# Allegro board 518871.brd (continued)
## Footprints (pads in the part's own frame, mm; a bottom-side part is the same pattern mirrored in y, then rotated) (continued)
JMP402-25
  rect 0.635x0.635 smd: 1(-0.508,0)
  round 0.635 smd: 2(0.508,0) 3(1.524,0)
JUMP1X2-6040
  rect 1.524x1.524 hole 1.016: 1(0,0)
  round 1.524 hole 1.016: 2(0,-2.54)
L603-35X45
  oval 0.889x1.143 smd: 1(-0.762,0) 2(0.762,0)
L805-35X60
  oval 0.889x1.524 smd: 1(-0.965,0) 2(0.965,0)
LED1206-59X59
  rect 1.499x1.499 smd: 1(-1.753,0) 2(1.753,0)
MHP125-250
  round 6.35 hole 3.175: 1(0,0)
MOLEX4-043650
  round 1.016 hole 2.997 unplated: (-6.833,-4.318) (-2.134,-4.318)
  rect 2.032x2.032 hole 1.041: 1(0,0)
  round 2.032 hole 1.041: 2(-2.997,0) 3(-5.994,0) 4(-8.992,0)
MOLEX-34826-0124
  round 1.524 hole 0.991: 1(-7.01,1.295) 2(-5.004,1.295) 3(5.004,1.295) 4(7.01,1.295) 5(-7.01,-0.914) 6(-5.004,-0.914) 7(-2.997,-0.914) 8(-0.991,-0.914) 9(0.991,-0.914) 10(2.997,-0.914) 11(5.004,-0.914) 12(7.01,-0.914)
  round 3.556 hole 2.54: 13(-9.855,0) 14(9.855,0)
MOLEX-502774-0891
  rect 0.787x1.778 smd: 1(-2.784,7.366) 2(-1.684,7.366) 3(-0.584,7.366) 4(0.516,7.366) 5(1.615,7.366) 6(2.715,7.366) 7(3.815,7.366) 8(4.915,7.366)
  rect 1.295x1.397 smd: 9(6.985,-1.6)
  rect 1.295x1.245 smd: 10(6.985,5.842)
  rect 1.778x2.032 smd: 11(6.858,-7.417) 12(-6.655,-7.391)
  rect 1.854x1.778 smd: 13(-6.35,7.468) 14(6.452,7.595)
PWR-Q5A-SLPS319
  rect 0.711x1.397 smd: 1(-1.905,0) 2(-0.635,0) 3(0.635,0) 4(1.905,0)
  custom 1.111x1.111 smd: 5(0,2.781)
QFN32_5X5
  oval 0.254x0.838 smd: 1(-1.751,-2.515) 8(1.751,-2.515) 17(1.751,2.515) 24(-1.751,2.515)
  rect 0.254x0.838 smd: 2(-1.251,-2.515) 3(-0.751,-2.515) 4(-0.25,-2.515) 5(0.25,-2.515) 6(0.751,-2.515) 7(1.251,-2.515) 18(1.251,2.515) 19(0.751,2.515) 20(0.25,2.515) 21(-0.25,2.515) 22(-0.751,2.515) 23(-1.251,2.515)
  oval 0.838x0.254 smd: 9(2.515,-1.751) 16(2.515,1.751) 25(-2.515,1.751) 32(-2.515,-1.751)
  rect 0.838x0.254 smd: 10(2.515,-1.251) 11(2.515,-0.751) 12(2.515,-0.25) 13(2.515,0.25) 14(2.515,0.751) 15(2.515,1.251) 26(-2.515,1.251) 27(-2.515,0.751) 28(-2.515,0.25) 29(-2.515,-0.25) 30(-2.515,-0.751) 31(-2.515,-1.251)
  rect 3.404x3.404 smd: 33(0,0)
QSH-020-DP-A
  round 0.508 hole 1.016 unplated: (-10.06,2.667) (10.06,2.667)
  rect 0.279x2.273 smd: 1(-7.248,-2.864) 2(-7.248,2.864) 3(-6.748,-2.864) 4(-6.748,2.864) 5(-5.749,-2.864) 6(-5.749,2.864) 7(-5.249,-2.864) 8(-5.249,2.864) 9(-4.249,-2.864) 10(-4.249,2.864) 11(-3.749,-2.864) 12(-3.749,2.864) 13(-2.749,-2.864) 14(-2.749,2.864) 15(-2.249,-2.864) 16(-2.249,2.864) 17(-1.25,-2.864) 18(-1.25,2.864) 19(-0.75,-2.864) 20(-0.75,2.864) 21(0.25,-2.864) 22(0.25,2.864) 23(0.75,-2.864) 24(0.75,2.864) 25(1.75,-2.864) 26(1.75,2.864) 27(2.249,-2.864) 28(2.249,2.864) 29(3.249,-2.864) 30(3.249,2.864) 31(3.749,-2.864) 32(3.749,2.864) 33(4.749,-2.864) 34(4.749,2.864) 35(5.249,-2.864) 36(5.249,2.864) 37(6.248,-2.864) 38(6.248,2.864) 39(6.748,-2.864) 40(6.748,2.864)
  rect 2.54x0.432 smd: 41(-8.065,0) 44(8.065,0)
  rect 4.699x0.432 smd: 42(-3.175,0) 43(3.175,0)
QSH-030-01-F
  round 0.508 hole 1.016 unplated: (-10.061,2.667) (10.061,2.667)
  rect 0.279x2.273 smd: 1(-7.249,-2.865) 2(-7.249,2.865) 3(-6.749,-2.865) 4(-6.749,2.865) 5(-6.248,-2.865) 6(-6.248,2.865) 7(-5.748,-2.865) 8(-5.748,2.865) 9(-5.248,-2.865) 10(-5.248,2.865) 11(-4.75,-2.865) 12(-4.75,2.865) 13(-4.249,-2.865) 14(-4.249,2.865) 15(-3.749,-2.865) 16(-3.749,2.865) 17(-3.249,-2.865) 18(-3.249,2.865) 19(-2.748,-2.865) 20(-2.748,2.865) 21(-2.25,-2.865) 22(-2.25,2.865) 23(-1.75,-2.865) 24(-1.75,2.865) 25(-1.25,-2.865) 26(-1.25,2.865) 27(-0.749,-2.865) 28(-0.749,2.865) 29(-0.249,-2.865) 30(-0.249,2.865) 31(0.249,-2.865) 32(0.249,2.865) 33(0.749,-2.865) 34(0.749,2.865) 35(1.25,-2.865) 36(1.25,2.865) 37(1.75,-2.865) 38(1.75,2.865) 39(2.25,-2.865) 40(2.25,2.865) 41(2.748,-2.865) 42(2.748,2.865) 43(3.249,-2.865) 44(3.249,2.865) 45(3.749,-2.865) 46(3.749,2.865) 47(4.249,-2.865) 48(4.249,2.865) 49(4.75,-2.865) 50(4.75,2.865) 51(5.248,-2.865) 52(5.248,2.865) 53(5.748,-2.865) 54(5.748,2.865) 55(6.248,-2.865) 56(6.248,2.865) 57(6.749,-2.865) 58(6.749,2.865) 59(7.249,-2.865) 60(7.249,2.865)
  rect 2.54x0.432 smd: 61(-8.065,0) 64(8.065,0)
  rect 4.699x0.432 smd: 62(-3.175,0) 63(3.175,0)
R201-6P6SPC
  rect 0.47x0.381 smd: 1(-0.343,0) 2(0.343,0)
R402-25
  round 0.635 smd: 1(-0.508,0) 2(0.508,0)
R603-35X45
  oval 0.889x1.143 smd: 1(-0.762,0) 2(0.762,0)
R0612
  rect 3.175x0.889 smd: 1(0,-0.813) 2(0,0.813)
R1206-40X70
  oval 1.016x1.778 smd: 1(-1.524,0) 2(1.524,0)
RGE24-11X28-4MM
  rect 0.711x0.279 smd: 1(-1.905,1.245) 2(-1.905,0.747) 3(-1.905,0.249) 4(-1.905,-0.249) 5(-1.905,-0.747) 6(-1.905,-1.245) 13(1.905,-1.245) 14(1.905,-0.747) 15(1.905,-0.249) 16(1.905,0.249) 17(1.905,0.747) 18(1.905,1.245)
  rect 0.279x0.711 smd: 7(-1.245,-1.905) 8(-0.747,-1.905) 9(-0.249,-1.905) 10(0.249,-1.905) 11(0.747,-1.905) 12(1.245,-1.905) 19(1.245,1.905) 20(0.747,1.905) 21(0.249,1.905) 22(-0.249,1.905) 23(-0.747,1.905) 24(-1.245,1.905)
  rect 2.464x2.464 smd: 25(0,0)
RKT24
  rect 0.203x0.965 smd: 1(-1.806,-0.965) 2(-1.405,-0.965) 3(-1.003,-0.965) 4(-0.602,-0.965) 5(-0.201,-0.965) 6(0.201,-0.965) 7(0.602,-0.965) 8(1.003,-0.965) 9(1.405,-0.965) 10(1.806,-0.965) 13(1.806,0.965) 14(1.405,0.965) 15(1.003,0.965) 16(0.602,0.965) 17(0.201,0.965) 18(-0.201,0.965) 19(-0.602,0.965) 20(-1.003,0.965) 21(-1.405,0.965) 22(-1.806,0.965)
  rect 0.965x0.203 smd: 11(1.981,-0.201) 12(1.981,0.201) 23(-1.981,0.201) 24(-1.981,-0.201)
RND36-24X10
  oval 0.254x0.61 smd: 1(-2.002,-2.896) 2(-1.501,-2.896) 3(-1.001,-2.896) 4(-0.5,-2.896) 5(0,-2.896) 6(0.498,-2.896) 7(0.998,-2.896) 8(1.499,-2.896) 9(1.999,-2.896) 19(2.002,2.896) 20(1.501,2.896) 21(1.001,2.896) 22(0.5,2.896) 23(0,2.896) 24(-0.498,2.896) 25(-0.998,2.896) 26(-1.499,2.896) 27(-1.999,2.896)
  oval 0.61x0.254 smd: 10(2.896,-2.002) 11(2.896,-1.501) 12(2.896,-1.001) 13(2.896,-0.5) 14(2.896,0) 15(2.896,0.498) 16(2.896,0.998) 17(2.896,1.499) 18(2.896,1.999) 28(-2.896,1.999) 29(-2.896,1.499) 30(-2.896,0.998) 31(-2.896,0.498) 32(-2.896,0) 33(-2.896,-0.5) 34(-2.896,-1.001) 35(-2.896,-1.501) 36(-2.896,-2.002)
  rect 3.81x3.81 smd: 37(0,0)
RTD64
  rect 0.711x0.279 smd: 1(-4.445,3.749) 2(-4.445,3.249) 3(-4.445,2.749) 4(-4.445,2.249) 5(-4.445,1.75) 6(-4.445,1.25) 7(-4.445,0.75) 8(-4.445,0.25) 9(-4.445,-0.25) 10(-4.445,-0.75) 11(-4.445,-1.25) 12(-4.445,-1.75) 13(-4.445,-2.249) 14(-4.445,-2.749) 15(-4.445,-3.249) 16(-4.445,-3.749) 33(4.445,-3.749) 34(4.445,-3.249) 35(4.445,-2.749) 36(4.445,-2.249) 37(4.445,-1.75) 38(4.445,-1.25) 39(4.445,-0.75) 40(4.445,-0.25) 41(4.445,0.25) 42(4.445,0.75) 43(4.445,1.25) 44(4.445,1.75) 45(4.445,2.249) 46(4.445,2.749) 47(4.445,3.249) 48(4.445,3.749)
  rect 0.279x0.711 smd: 17(-3.749,-4.445) 18(-3.249,-4.445) 19(-2.749,-4.445) 20(-2.249,-4.445) 21(-1.75,-4.445) 22(-1.25,-4.445) 23(-0.75,-4.445) 24(-0.25,-4.445) 25(0.25,-4.445) 26(0.75,-4.445) 27(1.25,-4.445) 28(1.75,-4.445) 29(2.249,-4.445) 30(2.749,-4.445) 31(3.249,-4.445) 32(3.749,-4.445) 49(3.749,4.445) 50(3.249,4.445) 51(2.749,4.445) 52(2.249,4.445) 53(1.75,4.445) 54(1.25,4.445) 55(0.75,4.445) 56(0.25,4.445) 57(-0.25,4.445) 58(-0.75,4.445) 59(-1.25,4.445) 60(-1.75,4.445) 61(-2.249,4.445) 62(-2.749,4.445) 63(-3.249,4.445) 64(-3.749,4.445)
  rect 5.588x5.588 smd: 65(0,0)
SAMTEC-MUSB
  round 0.508 hole 0.889 unplated: (-2.197,-2.591) (2.197,-2.591)
  rect 0.508x2.286 smd: 1(-1.6,0) 2(-0.8,0) 3(0,0) 4(0.8,0) 5(1.6,0)
  rect 2.007x2.489 smd: 6(-4.445,-0.102) 7(4.445,-0.102) 8(-4.445,-5.613) 9(4.445,-5.613)
SM-7351-CAP-0402
  round 0.635 smd: 1(-0.508,0) 2(0.508,0)
SM-7351-CAP-0508
  rect 0.457x1.778 smd: 1(-0.445,0) 2(0.445,0)
SM-7351-RES-0402
  round 0.635 smd: 1(-0.508,0) 2(0.508,0)
SMA2-78SQ
  rect 1.981x1.981 smd: 1(-2.007,0) 2(2.007,0)
SMC-80X128
  rect 2.032x3.251 smd: 1(-3.124,0) 2(3.124,0)
SO8-25X75-295
  oval 0.635x2.54 smd: 1(-1.905,-3.086) 2(-0.635,-3.086) 3(0.635,-3.086) 4(1.905,-3.086) 5(1.905,3.086) 6(0.635,3.086) 7(-0.635,3.086) 8(-1.905,3.086)
SO14-25X75
  oval 0.635x1.905 smd: 1(-3.81,-2.794) 2(-2.54,-2.794) 3(-1.27,-2.794) 4(0,-2.794) 5(1.27,-2.794) 6(2.54,-2.794) 7(3.81,-2.794) 8(3.81,2.794) 9(2.54,2.794) 10(1.27,2.794) 11(0,2.794) 12(-1.27,2.794) 13(-2.54,2.794) 14(-3.81,2.794)
SOD323
  rect 1.092x0.508 smd: 1(-1.194,0) 2(1.194,0)
SOT363-16X45
  rect 0.406x0.635 smd: 1(-0.65,-0.978) 2(0,-0.978) 3(0.65,-0.978) 4(0.65,0.978) 5(0,0.978) 6(-0.65,0.978)
SW2-30X50-TDA
  rect 0.762x1.27 smd: 1(-0.635,-3.81) 2(0.635,-3.81) 3(0.635,3.81) 4(-0.635,3.81)
SW6-30X50-TDA
  rect 0.762x1.27 smd: 1(-3.175,-3.81) 2(-1.905,-3.81) 3(-0.635,-3.81) 4(0.635,-3.81) 5(1.905,-3.81) 6(3.175,-3.81) 7(3.175,3.81) 8(1.905,3.81) 9(0.635,3.81) 10(-0.635,3.81) 11(-1.905,3.81) 12(-3.175,3.81)
TP1-70X135
  rect 2.286x3.937 smd: 1(0,0)
TP-30RD13
  round 0.762 hole 0.33: 1(0,0)
TSDSON8
  custom 0.248x0.248 smd: 1(-0.33,-1.499)
  rect 0.356x1.016 smd: 4(0.978,-1.486)
  custom 0.572x0.572 smd: 5(0,0.673)
unnamed
  round 1.27 smd: 1(0,0)
VFP0032B
  rect 1.346x0.508 smd: 1(-4.125,2.799) 2(-4.125,1.999) 3(-4.125,1.199) 4(-4.125,0.401) 5(-4.125,-0.401) 6(-4.125,-1.199) 7(-4.125,-1.999) 8(-4.125,-2.799) 17(4.125,-2.799) 18(4.125,-1.999) 19(4.125,-1.199) 20(4.125,-0.401) 21(4.125,0.401) 22(4.125,1.199) 23(4.125,1.999) 24(4.125,2.799)
  rect 0.508x1.346 smd: 9(-2.799,-4.125) 10(-1.999,-4.125) 11(-1.199,-4.125) 12(-0.401,-4.125) 13(0.401,-4.125) 14(1.199,-4.125) 15(1.999,-4.125) 16(2.799,-4.125) 25(2.799,4.125) 26(1.999,4.125) 27(1.199,4.125) 28(0.401,4.125) 29(-0.401,4.125) 30(-1.199,4.125) 31(-1.999,4.125) 32(-2.799,4.125)
  rect 4.826x4.826 smd: 33(0,0)
VQFNHR26
  custom 0.194x0.194 smd: 1(-1.816,2.038) 8(-1.816,-2.038) 14(1.81,-2.038) 21(1.81,2.038)
  rect 0.597x0.254 smd: 2(-1.899,1.25) 3(-1.899,0.749) 4(-1.899,0.249) 5(-1.899,-0.249) 6(-1.899,-0.749) 7(-1.899,-1.25) 15(1.899,-1.25) 16(1.899,-0.749) 17(1.899,-0.249) 18(1.899,0.249) 19(1.899,0.749) 20(1.899,1.25)
  rect 0.254x1.816 smd: 9(-1.001,-1.537) 10(-0.5,-1.537) 11(0,-1.537) 12(0.5,-1.537) 13(1.001,-1.537) 22(1.001,1.537) 23(0.5,1.537) 24(0,1.537) 25(-0.5,1.537) 26(-1.001,1.537)
  rect 2.235x0.66 smd: 27(0,0)
XTAL4-ABM11
  rect 0.889x0.813 smd: 1(-0.711,-0.559) 2(0.711,-0.559) 3(0.711,0.559) 4(-0.711,0.559)

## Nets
1V8_I2C1_SCL: P9.2 R245.2 U26.3(SCL1)
1V8_I2C1_SDA: P9.4 R246.2 U26.4(SDA1)
1V8_RSTOUTN: P9.14 R296.1 U31.M5(RSTN) U54.4(O)
GND: C1.2 C2.2 C3.2 C8.2 C23.2 C24.2 C29.2 C37.2 C38.2 C40.2 C41.1 C43.1 C45.2 C48.1 C51.1 C53.2 C54.1 C56.2 C59.2 C64.2 C71.2 C72.2 C73.2 C78.2 C81.2 C82.2 C83.2 C84.2 C89.2 C91.2 C96.2 C98.2 C108.2 C114.2 C118.2 C119.2 C120.2 C122.2 C129.2 C143.1 C144.1 C153.1 C154.1 C155.1 C156.1 C157.1 C158.1 C160.1 C161.1 C163.1 C164.1 C189.2 C194.2 C203.2 C204.2 C212.2 C267.2 C268.2 C269.2 C272.2 C273.2 C274.2 C275.1 C277.2 C278.2 C279.2 C280.2 C281.2 C282.2 C283.2 C284.2 C285.2 C286.2 C287.2 C288.2 C289.2 C293.2 C294.2 C295.2 C296.2 C297.2 C298.2 C299.2 C300.2 C301.2 C302.2 C303.2 C304.2 C305.2 C306.2 C307.2 C308.2 C309.2 C310.2 C311.2 C312.2 C313.2 C314.2 C315.2 C318.2 C319.2 C320.2 C321.2 C322.2 C323.2 C324.2 C325.2 C326.2 C327.2 C328.2 C329.2 C331.2 C332.2 C333.2 C334.2 C335.2 C336.2 C337.2 C338.2 C340.2 C341.2 C342.2 C343.2 C344.2 C345.2 C347.2 C348.2 C349.2 C351.2 C352.2 C354.2 C356.2 C357.2 C358.2 C359.2 C361.2 C362.2 C364.2 C367.2 C368.2 C369.2 C370.2 C372.2 C373.2 C374.2 C375.1 C377.2 C378.2 C379.2 C380.2 C382.2 C383.2 C385.2 C388.2 C390.2 C391.2 C392.2 C393.2 C394.2 C395.2 C401.2 C402.2 C403.2 C406.2 C407.2 C408.2 C409.2 C410.2 C411.2 C412.2 C426.2 C427.2 C428.2 C429.2 C430.2 C431.2 C432.2 C433.2 C434.2 C435.2 C436.2 C437.2 C442.1 C503.2 C506.2 C507.2 C508.2 C509.2 C511.2 C514.2 C518.2 C519.2 C521.2 C525.2 C536.2 C537.2 C540.2 C541.2 C542.2 C543.2 C544.2 C545.2 C546.2 C547.2 C551.2 C552.2 C553.2 C554.1 C556.2 C557.2 C558.2 C559.2 C560.2 C561.2 C562.2 C563.2 C565.2 C566.2 C567.2 C568.2 C569.1 C600.1 C601.2 C602.2 C603.1 C604.2 C605.2 C606.2 C607.2 C608.2 C609.2 C610.2 C611.1 C612.2 C613.2 C614.2 C615.2 C616.2 C617.1 C618.2 C619.2 C620.2 C621.2 C622.2 C623.2 C624.2 C625.2 C626.2 C627.2 C628.2 C629.2 C631.1 C632.1 C633.1 C634.1 C635.1 C638.1 C640.1 C641.1 C642.1 D21.1(CATHODE) D23.2(ANODE) D24.2(ANODE) D26.2(ANODE) D27.2(ANODE) DS1.1(CATHODE) E1.2 E2.2 E3.2 E4.2 E5.2 E6.2 E7.2 J1.2 J4.2 J7.5(USBVSS) J14.16(GND16) J14.57(GND57) J14.58(GND58) J14.61(GNDCT1) J14.62(GNDCT2) J14.63(GNDCT3) J14.64(GNDCT4) J17.5 J17.6 J17.11 J17.12 J25.1 J25.2 J25.8 J25.10 J25.12 J25.15 J25.18 J25.21 J25.24 J25.27 J25.30 J25.33 J25.36 J25.39 J25.40 J25.41(M1) J25.42(M2) J25.43(M3) J25.44(M4) J25.45(M5) J25.46(M6) J25.47(M7) J25.48(M8) J25.49(M9) J25.50(M10) M1.1 M2.1 M3.1 M4.1 P1.2(D2 SHIELD) P1.5(D1 SHIELD) P1.8(D0 SHIELD) P1.11(CK SHIELD) P1.17(GND) P1.MTG1 P1.MTG2 P1.MTG3 P1.MTG4 P9.12 P9.16 P9.24 P9.41(SH_GND.1) P9.42(SH_GND.2) P9.43(SH_GND.4) P9.44(SH_GND.3) P10.6(VSS) Q10.1(S) Q12.1(S2) Q12.4(S2) Q600.1(S2) Q600.4(S2) Q602.4(S2) R26.1 R32.2 R36.1 R39.1 R52.2 R56.1 R64.2 R76.2 R104.1 R118.1 R141.1 R222.1 R225.2 R235.2 R240.1 R244.1 R248.1 R251.2 R255.2 R259.2 R309.1 R330.2 R401.2 R409.2 R432.2 R437.2 R440.1 R441.1 R443.2 R444.2 R446.2 R448.1 R600.2 R603.1 R604.1 R608.1 R622.1 R623.1 RJ16.3 RJ17.3 RJ18.1 RJ19.1 RJ20.1 RJ21.1 RJ22.1 RJ23.1 RJ24.1 RJ25.1 RJ27.3 RJ28.3 RJ29.3 RJ30.3 TP16.1 TP17.1 TP39.1 TP60.1 TP63.1 TP64.1 TP65.1 TP66.1 U3.2(GND) U4.2(GND) U5.2(GND) U6.2(GND) U7.2(GND) U8.2(GND) U9.2(GND) U10.2(GND) U17.5(GND1) U17.13(GND2) U17.18(GND3) U18.3(AGND) U18.9(PGND) U18.25(DAP) U22.1(A0) U22.2(A1) U22.3(NC) U22.4(VSS) U23.A9(VSS.1) U23.B1(VSSQ.1) U23.B3(VSS.2) U23.B9(VSSQ.2) U23.D1(VSSQ.3) U23.D8(VSSQ.4) U23.E1(VSS.3) U23.E2(VSSQ.5) U23.E8(VSSQ.6) U23.F9(VSSQ.7) U23.G1(VSSQ.8) U23.G8(VSS.4) U23.G9(VSSQ.9) U23.J2(VSSDL) U23.J8(VSS.5) U23.M1(VSS.6) U23.M9(VSS.7) U23.P1(VSS.8) U23.P9(VSS.9) U23.T1(VSS.10) U23.T9(VSS.11) U26.1(GND) U27.A1(VSS_1) U27.A25(VSS_2) U27.AA7(VSS_78) U27.AA8(VSS_79) U27.AA9(VSS_80) U27.AA13(VSS_27) U27.AA15(VSS_86) U27.AB8(VSS_81) U27.AB11(VSSA_OSC1) U27.AC11(XI_OSC1) U27.AC13(VSS_82) U27.AE1(VSS_83) U27.AE15(VSS_84) U27.AE25(VSS_85) U27.G8(VSS_3) U27.G13(VSS_4) U27.G16(VSS_5) U27.H8(VSS_6) U27.H10(VSS_7) U27.H12(VSS_8) U27.H14(VSS_9) U27.H16(VSS_10) U27.H18(VSS_11) U27.H19(VSS_12) U27.J10(VSS_13) U27.J12(VSS_14) U27.J14(VSS_15) U27.J17(VSS_16) U27.K9(VSS_17) U27.K11(VSS_18) U27.K13(VSS_19) U27.K15(VSS_20) U27.K17(VSS_21) U27.L8(VSS_22) U27.L11(VSS_23) U27.L13(VSS_24) U27.L15(VSS_25) U27.L18(VSS_26) U27.M8(VSS_28) U27.M9(VSS_29) U27.M12(VSS_30) U27.M14(VSS_31) U27.M16(VSS_32) U27.M18(VSS_33) U27.M20(VSS_34) U27.N12(VSS_35) U27.N14(VSS_36) U27.N16(VSS_37) U27.N17(VSS_38) U27.N20(VSS_39) U27.P9(VSS_40) U27.P11(VSS_41) U27.P13(VSS_42) U27.P15(VSS_43) U27.P17(VSS_44) U27.P19(VSS_45) U27.R8(VSS_46) U27.R9(VSS_47) U27.R11(VSS_48) U27.R13(VSS_49) U27.R15(VSS_50) U27.R18(VSS_51) U27.R19(VSS_52) U27.T8(VSS_53) U27.T10(VSS_54) U27.T12(VSS_55) U27.T14(VSS_56) U27.T16(VSS_57) U27.T18(VSS_58) U27.U10(VSS_59) U27.U12(VSS_60) U27.U14(VSS_61) U27.U16(VSS_62) U27.U17(VSS_63) U27.U19(VSS_64) U27.V8(VSS_65) U27.V9(VSS_66) U27.V11(VSS_67) U27.V13(VSS_68) U27.V15(VSS_69) U27.V17(VSS_70) U27.V19(VSS_71) U27.W9(VSS_72) U27.W19(VSS_73) U27.Y7(VSS_74) U27.Y14(VSS_75) U27.Y16(VSS_76) U27.Y17(VSS_77) U29.A9(VSS.1) U29.B1(VSSQ.1) U29.B3(VSS.2) U29.B9(VSSQ.2) U29.D1(VSSQ.3) U29.D8(VSSQ.4) U29.E1(VSS.3) U29.E2(VSSQ.5) U29.E8(VSSQ.6) U29.F9(VSSQ.7) U29.G1(VSSQ.8) U29.G8(VSS.4) U29.G9(VSSQ.9) U29.J2(VSSDL) U29.J8(VSS.5) U29.M1(VSS.6) U29.M9(VSS.7) U29.P1(VSS.8) U29.P9(VSS.9) U29.T1(VSS.10) U29.T9(VSS.11) U31.G2(VSS.1) U31.G3(VSS.2) U31.G4(VSS.3) U31.G5(VSS.4) U31.G6(VSS.5) U31.G7(VSS.6) U31.G8(VSS.7) U31.G9(VSS.8) U31.H2(VSSQ.1) U31.H9(VSSQ.2) U31.J5(VSS.9) U31.L3(VSSQ.3) U31.L8(VSSQ.4) U31.M4(VSSQ.5) U31.M7(VSSQ.6) U31.P2(VSSQ.7) U31.P9(VSSQ.8) U35.4(PGND) U35.8(GND) U35.11(PWRPAD) U40.37(GND) U42.1(GND) U42.9(PAD) U52.4(GND.1) U52.17(GND.2) U52.20(GND.3) U52.24(AGND) U52.26(TEST) U52.33(PWRPAD) U54.2(I) U54.3(GND) U66.4(GND) U67.4(GND) U68.4(GND) U69.4(GND) U70.5(GND) U70.9(PWR_PAD) U76.2(GND) U77.11(RSVD) U77.25(IN_27) U77.65(DAP/GND) U78.1(SPI_SEL) U78.6(AVSS) U78.11(SPKVSS) U78.21(SCLK) U78.24(DVSS) U78.25(IOVSS) U79.2(GND) U600.5(GND) U600.7(PAD) U601.5(GND) U601.9(TPAD) U602.4(AGND1) U602.11(PGND_B01) U602.14(FB_B1) U602.17(AGND2) U602.24(PGND_B23) U602.27(AGND3) U603.2(GND) U604.4(GND) U605.2(GND) U606.10(SGND) U606.12(SYNC) U606.13(VSYNC) U606.20(IF) U606.23(LGND) U606.27(ISENSE_GND) U606.29(PGND) U606.33(EP) Y2.2(GND1) Y2.4(GND2)
GND_EARTH: J7.6(SHIELD1) J7.7(SHIELD2) J7.8(SHIELD3) J7.9(SHIELD4)
VBAT: C24.1 D22.1(CATHODE) J4.1 Q3.1(S1) Q3.2(S2) Q3.3(S3) U16.4(ANODE)
VBAT_SYS: C1.1 C2.1 C3.1 C23.1 C29.1 C37.1 C38.1 C552.1 C566.1 C620.1 C621.1 C622.1 C623.1 C624.1 L1.2 L604.1 Q9.5(D) R218.2 R430.2 R431.2 RJ27.1 TP1.1(TP) U18.15(VIN) U79.10(VSUP) U606.5(VSENSE_N) U606.6(VSENSE_P)
VCC_LED_30V: C625.1 C626.1 C627.1 C628.1 C629.1 C635.2 C636.1 C637.1 C639.1 C642.2 D25.CATHODE J24.2 J24.3 U606.26(FB)
VCC_LM5141: C45.1 D5.2(ANODE) U18.10(VCC)
VDD__TX: C122.1 C429.1 L17.1 U77.31(VDDTX)
VDD_CORE_AVS: C303.1 C321.1 C323.1 C332.1 C341.1 C344.1 C347.1 C348.1 C373.1 C551.1 C615.1 C616.1 L602.1(P1) L603.1(P1) U27.J15(VDD_1) U27.J16(VDD_2) U27.J18(VDD_3) U27.K12(VDD_4) U27.K18(VDD_5) U27.L12(VDD_6) U27.L17(VDD_7) U27.M11(VDD_8) U27.M13(VDD_9) U27.M15(VDD_10) U27.M17(VDD_11) U27.N11(VDD_12) U27.N13(VDD_13) U27.N15(VDD_14) U27.N18(VDD_15) U27.P10(VDD_16) U27.P12(VDD_17) U27.P14(VDD_18) U27.P16(VDD_19) U27.P18(VDD_20) U27.R10(VDD_21) U27.R12(VDD_22) U27.R14(VDD_23) U27.R16(VDD_24) U27.R17(VDD_25) U27.T9(VDD_26) U27.T11(VDD_27) U27.T13(VDD_28) U27.T15(VDD_29) U27.T17(VDD_30) U27.U9(VDD_31) U27.U11(VDD_32) U27.U13(VDD_33) U27.U15(VDD_34) U27.U18(VDD_35) U27.V10(VDD_36) U27.V12(VDD_37) U27.V14(VDD_38) U27.V16(VDD_39) U27.V18(VDD_40) U27.W10(VDD_41) U27.W12(VDD_42) U27.W14(VDD_43) U27.W16(VDD_44) U602.8(FB_B0)
VDD_CORE_SW0: L602.2(P2) U602.10(SW_B0)
VDD_CORE_SW1: L603.2(P2) U602.12(SW_B1)
VDD_DDR_1V35: C80.2 C84.1 C89.1 C96.1 C98.1 C143.2 C153.2 C155.2 C157.2 C272.1 C273.1 C274.1 C278.1 C279.1 C280.1 C289.1 C293.1 C294.1 C295.1 C297.1 C299.1 C300.1 C304.1 C305.1 C307.1 C311.1 C312.1 C313.1 C314.1 C315.1 C319.1 C325.1 C326.1 C327.1 C328.1 C336.1 C337.1 C338.1 C351.1 C352.1 C354.1 C377.1 C378.1 C382.1 C383.1 C386.2 C391.1 C392.1 C413.2 C414.2 C415.2 C416.2 C417.2 C418.2 C419.2 C420.2 C421.2 C422.2 C423.2 C424.2 C425.2 C601.1 L601.1(P1) R117.2 U23.A1(VDDQ.1) U23.A8(VDDQ.2) U23.B2(VDD.1) U23.C1(VDDQ.3) U23.C9(VDDQ.4) U23.D2(VDDQ.5) U23.D9(VDD.2) U23.E9(VDDQ.6) U23.F1(VDDQ.7) U23.G7(VDD.3) U23.H2(VDDQ.8) U23.H9(VDDQ.9) U23.K2(VDDL) U23.K8(VDD.4) U23.N1(VDD.5) U23.N9(VDD.6) U23.R1(VDD.7) U23.R9(VDD.8) U27.T19(VDDS_DDR1_1) U27.T20(VDDS_DDR1_2) U27.V20(VDDS_DDR1_3) U27.W17(VDDS_DDR1_4) U27.W18(VDDS_DDR1_5) U27.W20(VDDS_DDR1_6) U29.A1(VDDQ.1) U29.A8(VDDQ.2) U29.B2(VDD.1) U29.C1(VDDQ.3) U29.C9(VDDQ.4) U29.D2(VDDQ.5) U29.D9(VDD.2) U29.E9(VDDQ.6) U29.F1(VDDQ.7) U29.G7(VDD.3) U29.H2(VDDQ.8) U29.H9(VDDQ.9) U29.K2(VDDL) U29.K8(VDD.4) U29.N1(VDD.5) U29.N9(VDD.6) U29.R1(VDD.7) U29.R9(VDD.8) U35.2(VLDOIN) U602.21(FB_B3)
VDD_DDR_SW3: L601.2(P2) U602.23(SW_B3)
VDD_DSP_AVS: C357.1 C361.1 C362.1 C367.1 C368.1 C370.1 C385.1 C393.1 C401.1 C402.1 C403.1 C536.1 C537.1 C602.1 L600.1(P1) U27.H9(VDD_DSP_1) U27.H11(VDD_DSP_2) U27.H13(VDD_DSP_3) U27.J9(VDD_DSP_4) U27.J11(VDD_DSP_5) U27.J13(VDD_DSP_6) U602.1(FB_B2)
VDD_DSP_SW2: L600.2(P2) U602.25(SW_B2)
VDD_SPK: C562.1 C563.1 C565.1 L45.1 U78.8(LDO_SEL) U78.10(SPKVDD)
VDD_TAS: C558.1 C559.1 C560.1 C561.1 C567.1 U78.7(AVDD) U78.23(DVDD)
VDD_VID: C129.1 C409.1 C410.1 C568.1 L16.1 U77.16(VDDP) U77.28(VDD#28) U77.64(VDD#64)
VDDA_LM5141: C53.1 R34.2 R35.2 R221.2 U18.2(VDDA)
VDDI_MMC2: C433.1 C436.1 U31.E4(VDDIM)
VDDR_VREFSTL: C80.1 C82.1 C91.1 C164.2 C386.1 U23.H1(VREFDQ) U23.M8(VREFCA) U27.Y20(VREF_DDR1) U29.H1(VREFDQ) U29.M8(VREFCA) U35.6(REFOUT)
VDDS_1V8: C108.1 C283.1 C288.1 C298.1 C318.1 C335.1 C342.1 C369.1 C379.1 C380.1 C390.1 C411.1 C427.1 C428.1 C430.1 C431.1 C434.1 C603.2 L16.2 L17.2 P9.38 P9.40 R241.2 R243.2 R245.1 R246.1 R247.2 R250.1 R254.1 R258.1 R268.1 R269.1 R270.1 R271.1 R272.1 R273.1 R289.1 R291.1 R295.1 R296.2 R300.1 RJ16.1 RJ17.1 RJ18.3 RJ19.3 RJ20.3 RJ21.3 RJ22.3 RJ23.3 RJ24.3 RJ25.3 RJ28.1 RJ29.1 RJ30.1 U26.2(VREF1) U27.AA19(VDDS18V_DDR1_3) U27.F7(VDDSHV11_1) U27.G7(VDDSHV11_2) U27.G11(VDDS18V_1) U27.H7(VDDSHV11_3) U27.H20(VDDS18V_2) U27.J7(VDDSHV10_1) U27.J8(VDDSHV10_2) U27.K8(VDDSHV10_3) U27.P7(VDDS_MLB_1) U27.P20(VDDS18V_DDR1_1) U27.R7(VDDS_MLB_2) U27.W7(VDDS18V_3) U27.Y18(VDDS18V_4) U27.Y19(VDDS18V_DDR1_2) U31.H3(VCCQ.1) U31.H8(VCCQ.2) U31.L2(VCCQ.3) U31.L4(VCCQ.4) U31.L7(VCCQ.5) U31.L9(VCCQ.6) U31.P3(VCCQ.7) U31.P8(VCCQ.8) U600.1(OUT)
CAN_POWER_ON_HV: R436.1 SW2.4(B1)
CAN_WAKE: J17.10 R435.2 RJ27.2
CANH_1: J17.4 R388.1 U79.13(CANH)
CANL_1: J17.3 R152.2 U79.12(CANL)
CON_MMC1_CLK: P10.5(CLK) R406.2 U67.3(IO1)
CON_MMC1_CMD: P10.3(CMD) R405.2 U67.5(IO2)
CON_MMC1_DAT0: P10.7(DAT0) R407.2 U66.5(IO2)
CON_MMC1_DAT1: P10.8(DAT1) R408.2 U66.3(IO1)
CON_MMC1_DAT2: P10.1(DAT2) R403.2 U68.5(IO2)
CON_MMC1_DAT3: P10.2(DAT3) R404.2 U68.3(IO1)
CONN_USB_D+: J7.3(D+) U52.14(USBDP)
CONN_USB_D-: J7.2(D-) U52.15(USBDM)
EMAC[1]_RXC: U27.E11(VIN2A_D18/VIN2B_D5/RGMII1_RXC/V) U40.27(RX_CLK)
EMAC[1]_RXCTL: U27.F11(VIN2A_D19/VIN2B_D4/RGMII1_RXCTL) U40.15(RX_DV/CRS_DIV/RX_CTRL)
EMAC[1]_RXD0: U27.D13(VIN2A_D23/VIN2B_D0/RGMII1_RXD0/) U40.26(RX_D0)
EMAC[1]_RXD1: U27.C13(VIN2A_D22/VIN2B_D1/RGMII1_RXD1/) U40.25(RX_D1)
EMAC[1]_RXD2: U27.E13(VIN2A_D21/VIN2B_D2/RGMII1_RXD2/) U40.24(RX_D2)
EMAC[1]_RXD3: U27.B13(VIN2A_D20/VIN2B_D3/RGMII1_RXD3/) U40.23(RX_D3)
EMAC[1]_TXC: R101.1 U40.28(TX_CLK)
EMAC[1]_TXCTL: U27.D11(VIN2A_D13/RGMII1_TXCTL/VOUT2_D1) U40.29(TX_EN/TX_CTRL)
EMAC[1]_TXD0: U27.A13(VIN2A_D17/VIN2B_D6/RGMII1_TXD0/) U40.33(TX_D0)
EMAC[1]_TXD1: U27.A12(VIN2A_D16/VIN2B_D7/RGMII1_TXD1/) U40.32(TX_D1)
EMAC[1]_TXD2: U27.B12(VIN2A_D15/RGMII1_TXD2/VOUT2_D8/) U40.31(TX_D2)
EMAC[1]_TXD3: U27.C11(VIN2A_D14/RGMII1_TXD3/VOUT2_D9/) U40.30(TX_D3)
EMU_RSTN: J14.6(NRESET) R263.2 R329.2
EN_SDIO_3V3: R601.2 U27.Y1(MMC3_CMD/SPI3_SCLK/USB3_ULPI_D4) U604.1(EN1)
EN_STAGE1: C48.2 R401.1 SW2.1(A1) SW2.2(A2) U18.23(EN)
ENET_EN: R358.1 U27.A15(MCASP1_AXR4/MCASP4_AXR2/GPIO5_6) U40.7(EN)
ENET_INH: R365.1 U27.A17(MCASP1_AXR6/MCASP5_AXR2/GPIO5_8) U40.10(INH)
ENET_INTSN: R342.1 R346.1 U27.A16(MCASP1_AXR7/MCASP5_AXR3/TIMER4/)
ENET_WAKE: R360.1 U27.A14(MCASP1_AXR5/MCASP4_AXR3/GPIO5_7) U40.8(WAKE)
FB_5141: R24.1 R26.2 U18.19(FB)
GP6_10/EHRPWM2A: R610.2 U27.Y5(GPIO6_10/MDIO_MCLK/I2C3_SDA/USB) U606.17(NSS)
GP6_11/EHRPWM2B: Q602.5(G2) R611.2 U27.Y6(GPIO6_11/MDIO_D/I2C3_SCL/US3_UL) U606.18(PWM)
GPIO1_22/EHRPWM3A: R609.2 U27.Y3(MMC3_DAT4/SPI4_SCLK/UART10_RXD/) U606.11(FAULT)
GPIO7_2: R608.2 U27.W2(MMC3_DAT3/SPI3_CS1/UART5_RTSN/U) U606.19(VDDIO/EN)
H_CSI2_DX0: P9.5 U27.AC1(CSI2_0_DX0)
H_CSI2_DX1: P9.9 U27.AD1(CSI2_0_DX1)
H_CSI2_DX2: P9.13 U27.AE2(CSI2_0_DX2)
H_CSI2_DY0: P9.7 U27.AB2(CSI2_0_DY0)
H_CSI2_DY1: P9.11 U27.AC2(CSI2_0_DY1)
H_CSI2_DY2: P9.15 U27.AD2(CSI2_0_DY2)
H_DCAN1_EN: R438.1 U27.B17(MCASP1_AXR9/MCASP6_AXR1/SPI3_D1)
H_DCAN1_NFAULT: R439.1 U27.B16(MCASP1_AXR10/MCASP6_ACLKX/MCASP)
H_DCAN1_RX: R371.1 U27.H23(DCAN1_RX/UART8_TXD/MMC2_SDWP/HD)
H_DCAN1_STB: R426.1 U27.A18(MCASP1_AXR8/MCASP6_AXR0/SPI3_SC)
H_DCAN1_TX: R372.1 U27.H22(DCAN1_TX/UART8_RXD/MMC2_SDCD/HD)
H_DDR1_A0: R88.2 U23.N3(A0) U27.AC18(DDR1_A0) U29.N3(A0)
H_DDR1_A1: R284.2 U23.P7(A1) U27.AE19(DDR1_A1) U29.P7(A1)
H_DDR1_A2: R85.2 U23.P3(A2) U27.AD19(DDR1_A2) U29.P3(A2)
H_DDR1_A3: R90.2 U23.N2(A3) U27.AB19(DDR1_A3) U29.N2(A3)
H_DDR1_A4: R283.2 U23.P8(A4) U27.AD20(DDR1_A4) U29.P8(A4)
H_DDR1_A5: R287.2 U23.P2(A5) U27.AE20(DDR1_A5) U29.P2(A5)
H_DDR1_A6: R87.2 U23.R8(A6) U27.AA18(DDR1_A6) U29.R8(A6)
H_DDR1_A7: R288.2 U23.R2(A7) U27.AA20(DDR1_A7) U29.R2(A7)
H_DDR1_A8: R86.2 U23.T8(A8) U27.Y21(DDR1_A8) U29.T8(A8)
H_DDR1_A9: R84.2 U23.R3(A9) U27.AC20(DDR1_A9) U29.R3(A9)
H_DDR1_A10: R92.2 U23.L7(A10) U27.AA21(DDR1_A10) U29.L7(A10)
H_DDR1_A11: R285.2 U23.R7(A11) U27.AC21(DDR1_A11) U29.R7(A11)
H_DDR1_A12: R282.2 U23.N7(A12) U27.AC22(DDR1_A12) U29.N7(A12)
H_DDR1_A13: R83.2 U23.T3(A13) U27.AC15(DDR1_A13) U29.T3(A13)
H_DDR1_A14: R286.2 U23.T7(A14) U27.AB15(DDR1_A14) U29.T7(A14)
H_DDR1_A15: R281.2 U23.M7(NC.M7/A15) U27.AC16(DDR1_A15) U29.M7(NC.M7/A15)
H_DDR1_BA0: R280.2 U23.M2(BA0) U27.AE16(DDR1_BA0) U29.M2(BA0)
H_DDR1_BA1: R89.2 U23.N8(BA1) U27.AA16(DDR1_BA1) U29.N8(BA1)
H_DDR1_BA2: R91.2 U23.M3(BA2) U27.AB16(DDR1_BA2) U29.M3(BA2)
H_DDR1_CASN: R95.2 U23.K3(CAS#) U27.AD16(DDR1_CASN) U29.K3(CAS#)
H_DDR1_CKE: R279.2 U23.K9(CKE) U27.AB18(DDR1_CKE) U29.K9(CKE)
H_DDR1_CLK_N: R278.2 U23.K7(CK#) U27.AE21(DDR1_CKN) U29.K7(CK#)
H_DDR1_CLK_P: R94.2 U23.J7(CK) U27.AD21(DDR1_CKP) U29.J7(CK)
H_DDR1_CSN0: R93.2 U23.L2(CS#) U27.AC19(DDR1_CSN0) U29.L2(CS#)
H_DDR1_D0: U23.H7(DQ7) U27.AA23(DDR1_D0)
H_DDR1_D1: U23.F8(DQ3) U27.AC24(DDR1_D1)
H_DDR1_D2: U23.F7(DQ1) U27.AB24(DDR1_D2)
H_DDR1_D3: U23.H8(DQ5) U27.AD24(DDR1_D3)
H_DDR1_D4: U23.E3(DQ0) U27.AB23(DDR1_D4)
H_DDR1_D5: U23.H3(DQ4) U27.AC23(DDR1_D5)
H_DDR1_D6: U23.F2(DQ2) U27.AD23(DDR1_D6)
H_DDR1_D7: U23.G2(DQ6) U27.AE24(DDR1_D7)
H_DDR1_D8: U23.A2(DQ13) U27.AA24(DDR1_D8)
H_DDR1_D9: U23.B8(DQ14) U27.W25(DDR1_D9)
H_DDR1_D10: U23.A7(DQ12) U27.Y23(DDR1_D10)
H_DDR1_D11: U23.C8(DQ10) U27.AD25(DDR1_D11)
H_DDR1_D12: U23.C3(DQ9) U27.AC25(DDR1_D12)
H_DDR1_D13: U23.D7(DQ8) U27.AB25(DDR1_D13)
H_DDR1_D14: U23.A3(DQ15) U27.AA25(DDR1_D14)
H_DDR1_D15: U23.C2(DQ11) U27.W24(DDR1_D15)
H_DDR1_D16: U27.W23(DDR1_D16) U29.F8(DQ3)
H_DDR1_D17: U27.U25(DDR1_D17) U29.H8(DQ5)
H_DDR1_D18: U27.U24(DDR1_D18) U29.F7(DQ1)
H_DDR1_D19: U27.W21(DDR1_D19) U29.F2(DQ2)
H_DDR1_D20: U27.T22(DDR1_D20) U29.E3(DQ0)
H_DDR1_D21: U27.U22(DDR1_D21) U29.G2(DQ6)
H_DDR1_D22: U27.U23(DDR1_D22) U29.H7(DQ7)
H_DDR1_D23: U27.T21(DDR1_D23) U29.H3(DQ4)
H_DDR1_D24: U27.T23(DDR1_D24) U29.C3(DQ9)
H_DDR1_D25: U27.T25(DDR1_D25) U29.A7(DQ12)
H_DDR1_D26: U27.T24(DDR1_D26) U29.B8(DQ14)
H_DDR1_D27: U27.P21(DDR1_D27) U29.A3(DQ15)
H_DDR1_D28: U27.N21(DDR1_D28) U29.C8(DQ10)
H_DDR1_D29: U27.P22(DDR1_D29) U29.C2(DQ11)
H_DDR1_D30: U27.P23(DDR1_D30) U29.A2(DQ13)
H_DDR1_D31: U27.P24(DDR1_D31) U29.D7(DQ8)
H_DDR1_DQM0: U23.E7(LDM) U27.AE23(DDR1_DQM0)
H_DDR1_DQM1: U23.D3(UDM) U27.W22(DDR1_DQM1)
H_DDR1_DQM2: U27.U21(DDR1_DQM2) U29.E7(LDM)
H_DDR1_DQM3: U27.P25(DDR1_DQM3) U29.D3(UDM)
H_DDR1_DQS0_N: U23.G3(LDQS#) U27.AE22(DDR1_DQSN0)
H_DDR1_DQS0_P: U23.F3(LDQS) U27.AD22(DDR1_DQS0)
H_DDR1_DQS1_N: U23.B7(UDQS#) U27.Y25(DDR1_DQSN1)
H_DDR1_DQS1_P: U23.C7(UDQS) U27.Y24(DDR1_DQS1)
H_DDR1_DQS2_N: U27.V25(DDR1_DQSN2) U29.G3(LDQS#)
H_DDR1_DQS2_P: U27.V24(DDR1_DQS2) U29.F3(LDQS)
H_DDR1_DQS3_N: U27.R25(DDR1_DQSN3) U29.B7(UDQS#)
H_DDR1_DQS3_P: U27.R24(DDR1_DQS3) U29.C7(UDQS)
H_DDR1_ODT0: R276.2 U23.K1(ODT) U27.AD18(DDR1_ODT0) U29.K1(ODT)
H_DDR1_RASN: R96.2 U23.J3(RAS#) U27.AD17(DDR1_RASN) U29.J3(RAS#)
H_DDR1_RST: U23.T2(RSTN) U27.AE17(DDR1_RST) U29.T2(RSTN)
H_DDR1_WEN: R277.2 U23.L3(WE#) U27.AE18(DDR1_WEN) U29.L3(WE#)
H_DISPLAY_RSTN: J25.9 R444.1 U27.Y4(MMC3_DAT0/SPI3_D1/UART5_RXD/USB)
H_DS90C189_RSTN: R443.1 U27.L3(GPMC_A11/VIN1A_FLD0/VOUT3_FLD/V) U77.52(PDB)
H_EMU0: J14.19(TRD0.1) R310.2 U27.C21(EMU0/GPIO8_30)
H_EMU1: J14.21(TRD0.2) R311.2 U27.C22(EMU1/GPIO8_31)
H_EMU2: J14.13(TR_CLK0) R292.2
H_EMU3: J14.17(TRD0.0) U27.F14(EMU3)
H_EMU4: J14.23(TRD0.3) U27.F13(EMU4)
H_EMU5: J14.25(TRD0.4) U27.D8(VIN2A_CLK0/VOUT2_FLD/EMU5/KBD_R)
H_EMU6: J14.27(TRD0.5) U27.B7(VIN2A_DE0/VIN2A_FLD0/VIN2B_FLD1)
H_EMU7: J14.29(TRD0.6) U27.C7(VIN2A_FLD0/VIN2B_CLK1/VOUT2_CLK)
H_EMU8: J14.31(TRD0.7) U27.E8(VIN2A_HSYNC0/VIN2B_HSYNC1/VOUT2)
H_EMU9: J14.33(TRD0.8) U27.B8(VIN2A_VSYNC0/VIN2B_VSYNC1/VOUT2)
H_EMU10: J14.35(TRD0.9) U27.C8(VIN2A_D0/VOUT2_D23/EMU10/UART9_)
H_EMU11: J14.37(TRD3.0) U27.B9(VIN2A_D1/VOUT2_D22/EMU11/UART9_)
H_EMU12: J14.39(TRD3.1) U27.A7(VIN2A_D2/VOUT2_D21/EMU12/UART10)
H_EMU13: J14.41(TRD3.2) U27.A9(VIN2A_D3/VOUT2_D20/EMU13/UART10)
H_EMU14: J14.43(TRD3.3) U27.A8(VIN2A_D4/VOUT2_D19/EMU14/UART10)
H_EMU15: J14.45(TRD3.4) U27.A11(VIN2A_D5/VOUT2_D18/EMU15/UART10)
H_EMU16: J14.47(TRD3.5) U27.F10(VIN2A_D6/VOUT2_D17/EMU16/MII1_R)
H_EMU17: J14.49(TRD3.6) U27.A10(VIN2A_D7/VOUT2_D16/EMU17/MII1_R)
H_EMU18: J14.51(TRD3.7) U27.B10(VIN2A_D8/VOUT2_D15/EMU18/MII1_R)
H_EMU19: J14.53(TRD3.8) U27.E10(VIN2A_D9/VOUT2_D14/EMU19/MII1_R)
H_HDMI_CLKX: FL4.4 U27.AE9(HDMI1_CLOCKX)
H_HDMI_CLKY: FL4.1 U27.AD10(HDMI1_CLOCKY)
H_HDMI_DX0: FL8.4 U27.AE11(HDMI1_DATA0X)
H_HDMI_DX1: FL7.4 U27.AE12(HDMI1_DATA1X)
H_HDMI_DX2: FL3.4 U27.AE14(HDMI1_DATA2X)
H_HDMI_DY0: FL8.1 U27.AD12(HDMI1_DATA0Y)
H_HDMI_DY1: FL7.1 U27.AD13(HDMI1_DATA1Y)
H_HDMI_DY2: FL3.1 U27.AD15(HDMI1_DATA2Y)
H_I2C1_SCL: R234.1 U22.6(SCL) U26.6(SCL2) U27.G22(I2C1_SCL) U78.19(SCL/SSZ) U602.5(SCL) U606.16(SCLK/SCL)
H_I2C1_SDA: R233.1 U22.5(SDA) U26.5(SDA2) U27.G23(I2C1_SDA) U78.20(SDA/MOSI) U602.6(SDA) U606.15(MOSI/SDA)
H_JTAG_RTCK: J14.7(RTCK) R70.2
H_JTAG_TCK: J14.3(TCK) R307.2 U27.K21(TCLK)
H_JTAG_TDI: J14.5(TDI) U27.L23(TDI/GPIO8_27)
H_JTAG_TDO: J14.4(TDO) R264.2
H_JTAG_TMS: J14.2(TMS) R328.2 U27.L21(TMS)
H_JTAG_TRSTN: RJ26.2 U27.L22(TRSTN)
H_MCASP4_ACLKX: R97.1 U78.15(BCLK)
H_MCASP4_AXR0: U27.A24(MCASP4_AXR0/SPI3_D0/UART8_CTSN/) U78.13(DIN)
H_MCASP4_AXR1: U27.D23(MCASP4_AXR1/SPI3_CS0/UART8_RTSN) U78.18(GPIO/DOUT)
H_MCASP4_FSX: U27.B25(MCASP4_FSX/MCASP4_FSR/SPI3_D1/U) U78.14(WCLK)
H_MMC1_CLK: R66.1 R226.2 R406.1
H_MMC1_CMD: R227.2 R405.1 U27.V4(MMC1_CMD/GPIO6_22)
H_MMC1_D0: R228.2 R407.1 U27.V3(MMC1_D0/GPIO6_23)
H_MMC1_D1: R230.2 R408.1 U27.V2(MMC1_D1/GPIO6_24)
H_MMC1_D2: R231.2 R403.1 U27.W1(MMC1_D2/GPIO6_25)
H_MMC1_D3: R229.2 R404.1 U27.V1(MMC1_D3/GPIO6_26)
H_MMC1_SDCD: R410.2 R411.1 U27.U5(MMC1_SDCD/UART6_RXD/I2C4_SDA/GP)
H_NMIN_DSP: R71.2 U27.L24(NMIN_DSP)
H_PMIC_INTN: R236.1 U27.AB10(WAKEUP3/SYS_NIRQ1/GPIO1_3/DCAN2) U602.19(NINT)
H_PORZ: R602.2 TP40.1(TP) U27.F19(PORZ) U40.3(RESET_N) U602.2(EN3/GPIO3) U602.16(PGOOD)
H_RSTOUTN: R104.2 TP36.1(TP) U27.E20(RSTOUTN) U54.1(OE)
H_TAS2505_RSTN: R437.1 U27.F24(SPI2_CS0/UART3_RTSN/UART5_TXD/G) U78.2(RSTN)
H_UART3_RXD_BOOT: R232.1 U27.N22(UART2_CTSN/UART3_IRRX/MMC4_DAT2)
H_UART3_TXD_BOOT: R56.2 U27.N24(UART2_RTSN/UART3_TXD/UART3_IRTX) U52.2(RXD)
H_XREF_CLK3: R75.2 U78.16(MCLK)
HDMI_CEC_A: U17.24(CEC_A) U27.AB1(MMC3_DAT7/SPI4_CS0/UART10_RTSN/)
HDMI_CEC_B: P1.13(CE REMOTE) R27.1 U17.6(CEC_B)
HDMI_DSCL: R212.1 R265.1 U17.1(SCL_A)
HDMI_DSDA: R215.1 R266.1 U17.2(SDA_A)
HDMI_HPD: R25.1 U27.AA1(MMC3_DAT5/SPI4_D1/UART10_TXD/US)
HDMI_HPD_B: P1.19(HP DET) R31.2 R32.1 U17.9(HPD_B)
HDMI_SCL_B: P1.15(DDC CLK) R28.1 U17.7(SCL_B)
HDMI_SDA_B: P1.16(DDC DATA) R30.1 U17.8(SDA_B)
HDMI_TX0+: FL8.2 P1.7(D0+) U9.1(IO)
HDMI_TX0-: FL8.3 P1.9(D0-) U10.1(IO)
HDMI_TX1+: FL7.2 P1.4(D1+) U7.1(IO)
HDMI_TX1-: FL7.3 P1.6(D1-) U8.1(IO)
HDMI_TX2+: FL3.2 P1.1(D2+) U3.1(IO)
HDMI_TX2-: FL3.3 P1.3(D2-) U4.1(IO)
HDMI_TXC+: FL4.2 P1.10(CK+) U5.1(IO)
HDMI_TXC-: FL4.3 P1.12(CK-) U6.1(IO)
LED_K1: D26.1(CATHODE) J24.1 R625.1
LED_K2: D27.1(CATHODE) J24.4 R626.1
LP87523_REGEN_3V3: Q600.2(G2) R603.2 U42.6(EN) U601.3(ON) U602.15(EN2/GPIO2) U604.3(EN2) U605.3(EN)
MDIO_MDCLK: U27.D10(VIN2A_D10/MDIO_MCLK/VOUT2_D13/K) U40.1(MDC)
MDIO_MDIO: R344.2 U27.C10(VIN2A_D11/MDIO_D/VOUT2_D12/KBD_) U40.36(MDIO)
MMC2_CLK: R99.1 R299.1 R300.2
MMC2_CMD: R295.2 U27.A6(GPMC_CS1/MMC2_CMD/GPMC_A22/VIN2) U31.P5(CMD)
MMC2_DAT0: R273.2 U27.D7(GPMC_A24/MMC2_DAT0/GPMC_A18/VIN) U31.K2(DAT0)
MMC2_DAT1: R271.2 U27.C6(GPMC_A25/MMC2_DAT1/GPMC_A19/VIN) U31.N2(DAT1)
MMC2_DAT2: R269.2 U27.A5(GPMC_A26/MMC2_DAT2/GPMC_A20/VIN) U31.K3(DAT2)
MMC2_DAT3: R291.2 U27.B6(GPMC_A27/MMC2_DAT3/GPMC_A21/VIN) U31.N3(DAT3)
MMC2_DAT4: R289.2 U27.A4(GPMC_A19/MMC2_DAT4/GPMC_A13/VIN) U31.N8(DAT4)
MMC2_DAT5: R272.2 U27.E7(GPMC_A20/MMC2_DAT5/GPMC_A14/VIN) U31.K8(DAT5)
MMC2_DAT6: R270.2 U27.D6(GPMC_A21/MMC2_DAT6/GPMC_A15/VIN) U31.N9(DAT6)
MMC2_DAT7: R268.2 U27.C5(GPMC_A22/MMC2_DAT7/GPMC_A16/VIN) U31.K9(DAT7)
MMC_PWR_ON: R412.2 U27.Y2(MMC3_CLK/USB3_ULPI_D5/VIN2B_D7/) U70.3(ON)
NOT_GP6_11/EHRPWM2B: J1.1 Q602.3(D2) R619.2
NTRST: J14.9(NTRST) R312.2 RJ26.3
PMIC_REGEN_LP87523: R217.1 R433.2 R604.2 TP12.1(TP) U18.21(PG) U602.7(EN1/GPIO1)
RXEIN0+: J25.22 U77.39(OB_0+)
RXEIN0-: J25.23 U77.40(OB_0-)
RXEIN1+: J25.19 U77.37(OB_1+)
RXEIN1-: J25.20 U77.38(OB_1-)
RXEIN2+: J25.16 U77.35(OB_2+)
RXEIN2-: J25.17 U77.36(OB_2-)
RXEIN3+: J25.13 U77.30(OB_3+)
RXEIN3-: J25.14 U77.32(OB_3-)
RXOCLKIN+: J25.28 U77.43(OA_C+)
RXOCLKIN-: J25.29 U77.44(OA_C-)
RXOIN0+: J25.37 U77.50(OA_0+)
RXOIN0-: J25.38 U77.49(OA_0-)
RXOIN1+: J25.34 U77.48(OA_1+)
RXOIN1-: J25.35 U77.47(OA_1-)
RXOIN2+: J25.31 U77.46(OA_2+)
RXOIN2-: J25.32 U77.45(OA_2-)
RXOIN3+: J25.25 U77.41(OA_3+)
RXOIN3-: J25.26 U77.42(OA_3-)
SPK_N: J17.8 U78.9(SPKM)
SPK_P: J17.7 U78.12(SPKP)
SWP1: R258.2 SW1.1(A1)
SWP2: R254.2 SW1.2(A2)
SWP3: R250.2 SW1.3(A3)
SWP4: R248.2 SW1.4(A4)
SWP5: R244.2 SW1.5(A5)
SWP6: R240.2 SW1.6(A6)
TRD1_N: C233.1 J17.2 R449.1
TRD1_P: C232.1 J17.1 R450.1
TRD_N: L44.3 U40.13(TRD_N)
TRD_P: L44.4 U40.12(TRD_P)
TRSTPD: J14.8(TRSTPD) R330.1 RJ26.1
VCAP_VBBLDO_DSP: C388.1 U27.F8(CAP_VBBLDO_DSP)
VCAP_VBBLDO_GPU: C329.1 U27.T7(CAP_VBBLDO_GPU)
VCAP_VBBLDO_IVA: C395.1 U27.G14(CAP_VBBLDO_IVA)
VCAP_VBBLDO_MPU: C394.1 U27.F17(CAP_VBBLDO_MPU)
VCAP_VDDRAM_CORE1: C322.1 U27.U20(CAP_VDDRAM_CORE1)
VCAP_VDDRAM_CORE3: C358.1 U27.K7(CAP_VDDRAM_CORE3)
VCAP_VDDRAM_CORE4: C412.1 U27.G19(CAP_VDDRAM_CORE4)
VCAP_VDDRAM_DSP: C334.1 U27.L7(CAP_VDDRAM_DSP)
VCAP_VDDRAM_GPU: C320.1 U27.V7(CAP_VDDRAM_GPU)
VCAP_VDDRAM_IVA: C426.1 U27.G12(CAP_VDDRAM_IVA)
VCAP_VDDRAM_MPU: C374.1 U27.G18(CAP_VDDRAM_MPU)
VDA_COREGMACVID_FIL1V8: C359.1 C372.1 E5.3 U27.K10(VDDA_DSP_IVA_1) U27.L9(VDDA_CORE_GMAC) U27.L10(VDDA_DSP_IVA_2)
VDA_CSI_FIL1V8: C324.1 C333.1 E3.3 U27.T6(VDDA_CSI)
VDA_DDRDBGGPUPER_FIL1V8: C340.1 C343.1 E4.3 U27.M10(VDDA_PER) U27.N9(VDDA_GPU) U27.N10(VDDA_DEBUG)
VDA_HDMI_FIL1V8: C301.1 C308.1 C310.1 E2.3 U27.W11(VDDA_PCIE_1) U27.W15(VDDA_HDMI_1) U27.Y11(VDDA_PCIE_2) U27.Y15(VDDA_HDMI_2)
VDA_MPU_ABE_FIL1V8: C349.1 C407.1 E7.3 U27.K16(VDDA_MPU_ABE_1) U27.L16(VDDA_MPU_ABE_2)
VDA_OSC_FIL1V8: C286.1 C309.1 E1.3 U27.W13(VDDA_OSC_1) U27.Y13(VDDA_OSC_2)
VDA_PHY_1V8: C302.1 C306.1 C618.1 E2.1 E3.1 U27.W8(VDDA_USB_1) U27.Y8(VDDA_USB_2) U27.Y9(VDDA_USB_3) U605.5(OUT)
VDA_PLL_1V8: C331.1 C406.1 C609.1 E1.1 E4.1 E5.1 E6.1 E7.1 U27.R20(VDDA_DDR) U603.5(OUT)
VDA_SDIO_DV: C345.1 C611.2 R226.1 R227.1 R228.1 R229.1 R230.1 R231.1 R410.1 R605.2 U27.N8(VDDSHV8_1) U27.P8(VDDSHV8_2) U604.5(OUT2) U604.6(OUT1)
VDA_VIDEO_FIL1V8: C364.1 C408.1 E6.3 U27.K14(VDDA_VIDEO_1) U27.L14(VDDA_VIDEO_2)
VHDMI_5V0: C268.1 P1.18(+5V) U17.12(5V_OUT)
VIO_3V3: C83.1 C114.1 C118.1 C119.1 C120.1 C189.1 C212.1 C267.1 C275.2 C277.1 C281.1 C282.1 C284.1 C285.1 C287.1 C296.1 C356.1 C432.1 C435.1 C437.1 C442.2 C507.1 C508.1 C509.1 C511.1 C518.1 C519.1 C521.1 C546.1 C556.1 C557.1 C604.1 C632.2 C633.2 C641.2 J25.3 J25.4 J25.5 J25.6 J25.7 L45.2 P9.30 P9.32 P9.34 P9.36 R27.2 R33.1 R55.1 R71.1 R212.2 R215.2 R216.1 R233.2 R234.2 R236.2 R249.1 R262.2 R307.1 R308.1 R310.1 R311.1 R312.1 R328.1 R329.1 R342.2 R344.1 R358.2 R360.2 R365.2 R382.1 R412.1 R447.2 R601.1 R602.1 R609.1 R610.1 R611.1 R619.1 TP600.1(TP) U17.23(VCCA) U22.8(VCC) U27.AA10(VDDA33V_USB_1) U27.G9(VDDSHV1_1) U27.G10(VDDSHV1_2) U27.G15(VDDSHV3_1) U27.G17(VDDSHV3_2) U27.H15(VDDSHV3_3) U27.H17(VDDSHV3_4) U27.J19(VDDSHV3_5) U27.K19(VDDSHV3_6) U27.M7(VDDSHV9_1) U27.M19(VDDSHV4_1) U27.N7(VDDSHV9_2) U27.N19(VDDSHV4_2) U27.U7(VDDSHV7_1) U27.U8(VDDSHV7_2) U27.Y10(VDDA33V_USB_2) U31.F2(VCC.1) U31.F3(VCC.2) U31.F4(VCC.3) U31.F5(VCC.4) U31.F6(VCC.5) U31.F7(VCC.6) U31.F8(VCC.7) U31.F9(VCC.8) U40.11(VDDA) U40.22(VDDIO) U52.1(VCCIO.1) U54.5(VCC) U70.1(VIN.1) U70.2(VIN.2) U78.22(IOVDD) U79.5(VIO) U601.7(VOUT2) U601.8(VOUT1) U606.3(VDD)
VIO_3V3_SD: C540.1 C541.1 C542.1 C544.1 C545.1 P10.4(VDD) U66.1(VCC) U67.1(VCC) U68.1(VCC) U70.7(VOUT.2) U70.8(VOUT.1)
VOUT3B_CLK: R445.1 U77.6(IN_CLK)
VOUT3B_D0: R259.1 SW1.12(B1) U27.F1(GPMC_AD0/VIN1A_D0/VOUT3_D0/GPIO) U77.4(IN_12)
VOUT3B_D1: R255.1 SW1.11(B2) U27.E2(GPMC_AD1/VIN1A_D1/VOUT3_D1/GPIO) U77.5(IN_13)
VOUT3B_D2: R251.1 SW1.10(B3) U27.E1(GPMC_AD2/VIN1A_D2/VOUT3_D2/GPIO) U77.7(IN_14)
VOUT3B_D3: R247.1 SW1.9(B4) U27.C1(GPMC_AD3/VIN1A_D3/VOUT3_D3/GPIO) U77.8(IN_15)
VOUT3B_D4: R243.1 SW1.8(B5) U27.D1(GPMC_AD4/VIN1A_D4/VOUT3_D4/GPIO) U77.9(IN_16)
VOUT3B_D5: R241.1 SW1.7(B6) U27.D2(GPMC_AD5/VIN1A_D5/VOUT3_D5/GPIO) U77.10(IN_17)
VOUT3B_D6: RJ25.2 U27.B1(GPMC_AD6/VIN1A_D6/VOUT3_D6/GPIO) U77.23(IN_25)
VOUT3B_D7: RJ24.2 U27.B2(GPMC_AD7/VIN1A_D7/VOUT3_D7/GPIO) U77.24(IN_26)
VOUT3B_D8: RJ17.2 U27.C2(GPMC_AD8/VIN1A_D8/VOUT3_D8/GPIO) U77.60(IN_6)
VOUT3B_D9: RJ16.2 U27.D3(GPMC_AD9/VIN1A_D9/VOUT3_D9/GPIO) U77.61(IN_7)
VOUT3B_D10: RJ20.2 U27.A2(GPMC_AD10/VIN1A_D10/VOUT3_D10/G) U77.62(IN_8)
VOUT3B_D11: RJ21.2 U27.B3(GPMC_AD11/VIN1A_D11/VOUT3_D11/G) U77.1(IN_9)
VOUT3B_D12: RJ19.2 U27.C3(GPMC_AD12/VIN1A_D12/VOUT3_D12/G) U77.2(IN_10)
VOUT3B_D13: RJ22.2 U27.C4(GPMC_AD13/VIN1A_D13/VOUT3_D13/G) U77.3(IN_11)
VOUT3B_D14: RJ18.2 U27.A3(GPMC_AD14/VIN1A_D14/VOUT3_D14/G) U77.21(IN_23)
VOUT3B_D15: RJ23.2 U27.B4(GPMC_AD15/VIN1A_D15/VOUT3_D15/G) U77.22(IN_24)
VOUT3B_D16: U27.M1(GPMC_A0/VIN1A_D16/VOUT3_D16/VIN) U77.53(IN_0)
VOUT3B_D17: U27.M2(GPMC_A1/VIN1A_D17/VOUT3_D17/VIN) U77.55(IN_1)
VOUT3B_D18: U27.L2(GPMC_A2/VIN1A_D18/VOUT3_D18/VIN) U77.56(IN_2)
VOUT3B_D19: U27.L1(GPMC_A3/QSPI1_CS2/VIN1A_D19/VOU) U77.57(IN_3)
VOUT3B_D20: U27.K3(GPMC_A4/QSPI1_CS3/VIN1A_D20/VOU) U77.58(IN_4)
VOUT3B_D21: U27.K2(GPMC_A5/VIN1A_D21/VOUT3_D21/VIN) U77.59(IN_5)
VOUT3B_D22: U27.J1(GPMC_A6/VIN1A_D22/VOUT3_D22/VIN) U77.19(IN_21)
VOUT3B_D23: U27.K1(GPMC_A7/VIN1A_D23/VOUT3_D23/VIN) U77.20(IN_22)
VOUT3B_DE: U27.J2(GPMC_A10/VIN1A_DE0/VOUT3_DE/VIN) U77.18(DE)
VOUT3B_HSYNC: U27.K4(GPMC_A8/VIN1A_HSYNC0/VOUT3_HSYN) U77.12(HS)
VOUT3B_VSYNC: U27.H1(GPMC_A9/VIN1A_VSYNC0/VOUT3_VSYN) U77.13(VS)
VREF_DBG: J14.1(VREF_DBG) J14.12(VREF_TR) R308.2
VSYS_3V3: C56.1 C59.1 C64.1 C163.2 C194.1 C554.2 C600.2 C605.1 C606.1 C607.1 C610.1 C612.1 C613.1 C614.1 C619.1 L6.2 L34.1 R22.2 R23.2 R128.2 R129.2 R217.2 U35.10(VIN) U42.4(ILM) U42.8(VIN) U76.4(VDD) U600.4(EN) U600.6(IN) U601.1(VIN1) U601.2(VIN2) U602.9(VIN_B0) U602.13(VIN_B1) U602.18(VANA) U602.20(NRST) U602.22(VIN_B3) U602.26(VIN_B2) U603.1(IN) U603.3(EN) U605.1(IN)
VSYS_5V0: C203.1 C204.1 C220.1 C269.1 C514.1 C617.2 R28.2 R30.2 R31.1 R140.2 R143.2 R606.2 TP51.1(TP) U17.10(VCC5V) U18.16(VCCX) U42.2(VOUT) U70.4(VBIAS) U79.3(VCC) U601.4(VBIAS) U604.2(IN)
VTT_DDR: C144.2 C154.2 C156.2 C158.2 C413.1 C414.1 C415.1 C417.1 C418.1 C419.1 C420.1 C421.1 C422.1 C423.1 C424.1 C425.1 R83.1 R84.1 R85.1 R86.1 R87.1 R88.1 R89.1 R90.1 R91.1 R92.1 R93.1 R95.1 R96.1 R120.2 R276.1 R277.1 R279.1 R280.1 R281.1 R282.1 R283.1 R284.1 R285.1 R286.1 R287.1 R288.1 U35.3(VO)
N16778201: P10.9(INSERT) R411.2 U69.5(IO2)
N16778260: P10.10(INSERT_COM) R409.1
N16778400: C543.1 U69.1(VCC)
N16778910: C547.1 U70.6(CT)
N22073312: R299.2 U31.P6(CLK)
N22234321: R266.2 U27.G21(I2C2_SCL/HDMI1_DDC_SDA)
N22234323: R265.2 U27.F23(I2C2_SDA/HDMI1_DDC_SCL)
N26762656: R216.2 U17.4(LS_OE)
N26762977: R33.2 U17.11(CT_HPD)
N27139839: R264.1 U27.J20(TDO/GPIO8_28)
N27139840: R70.1 U27.K25(RTCK/GPIO8_29)
N27143878: R75.1 U27.H25(XREF_CLK3/MCASP2_AXR11/MCASP1_A)
N27144522: R66.2 U27.U3(MMC1_CLK/GPIO6_21)
N27225962: R292.1 U27.E14(EMU2)
N27380264: J14.15(TGT_DETECT) R309.2
N27473363: R25.2 U17.3(HPD_A)
N29751222: C81.1 U52.16(3V3OUT)
N29751238: C73.1 C78.1 L9.2 U52.19(VCC)
N29751250: C71.1 J7.1(USBVDD) L9.1 R51.2
N29751338: C72.1 R51.1 R52.1 U52.18(RESET#)
N29751389: R55.2 U52.11(CBUS3)
N29751493: R232.2 U52.30(TXD)
N30095792: R346.2 U40.2(INT_N)
N30095794: TP49.1(TP) U40.16(CLK_OUT/GPIO_2)
N30127037: R97.2 U27.C23(MCASP4_ACLKX/MCASP4_ACLKR/SPI3_)
N30256264: R64.1 U23.L8(ZQ)
N30256273: R76.1 U29.L8(ZQ)
N30257754: C160.2 R117.1 R118.2 U35.1(REFIN)
N30258027: R128.1 U35.7(EN)
N30258029: R129.1 U35.9(PGOOD)
N30258277: C161.2 R120.1 U35.5(VOSNS)
N30258482: C416.1 R94.1 R278.1
N30411655: R235.1 TP18.1(TP) U22.7(WP)
N30491879: C276.2 C292.2 U27.AA12(VSSA_OSC0) Y3.2(GND1) Y3.4(GND2)
N30491883: C292.1 U27.Y12(XI_OSC0) Y3.3(C1)
N30491911: C276.1 U27.AB12(XO_OSC0) Y3.1(Y1)
N30492439: C506.1 U40.5(XI) Y2.3(C1)
N30492465: C503.1 U40.4(XO) Y2.1(Y1)
N30512853: C232.2 L44.1
N30512862: C233.2 L44.2
N31206842: Q3.4(G) U16.2(GT PULL DWN) U16.6(GATE DRV)
N31206856: C30.1 U16.1(VCAPL)
N31206860: C30.2 U16.7(VCAPH)
N31206880: C8.1 L1.1 Q3.5(D1) R202.2 U16.8(CATHODE)
N31207093: D21.2(ANODE) D22.2(ANODE)
N31207095: DS1.2(ANODE) R202.1
N31208453: R213.2 U18.13(HO)
N31208462: R214.1 U18.14(HOL)
N31208471: R219.2 U18.8(LO)
N31208480: R220.1 U18.7(LOL)
N31208503: Q10.4(G) R219.1 R220.2
N31208524: Q9.4(G) R213.1 R214.2
N31208551: C39.1 C270.2 D23.1(CATHODE) L6.1 Q9.1(S) Q10.5(D) R18.1 U18.12(SW)
N31208672: C39.2 D5.1(CATHODE) U18.11(HB)
N31208960: C270.1 R225.1
N31209649: C36.2 R18.2 R428.1 U18.18(CS)
N31209654: C36.1 R22.1 R428.2 U18.17(VOUT)
N31222024: R39.2 R221.1 U18.1(DEMB)
N31222132: C41.2 R29.1
N31222198: C40.1 R29.2 U18.20(COMP)
N31222241: C51.2 U18.24(RES)
N31222246: C43.2 U18.22(SS)
N31222265: R35.1 R36.2 U18.6(OSC)
N31222285: C54.2 R34.1 U18.5(DITH)
N31222303: R222.2 U18.4(RT)
N31222717: R23.1 R24.2
N31975868: TP32.1(TP) U27.F20(RSV_VPP)
N32593135: R99.2 U27.B5(GPMC_A23/MMC2_CLK/GPMC_A17/VIN2)
N32595277: C375.2 R262.1 R263.1 U27.K24(RESETN)
N33095449: Q12.3(D2) R433.1 U76.3(RESETN)
N33095497: C553.1 D24.1(CATHODE) Q12.2(G2) R431.1 R432.1 U76.5(SENSE)
N33095499: Q12.5(G2) Q12.6(D2) R430.1
N33309281: R372.2 U79.1(TXD)
N33309290: C525.1 R152.1 R388.2
N33309297: R371.2 U79.4(RXD)
N33309347: R426.2 R441.2 U79.14(NSTB)
N33312629: R435.1 U79.9(WAKE)
N33314378: R436.2 R446.1 U79.7(INH)
N33322259: R438.2 R440.2 U79.6(EN)
N33322262: R382.2 R439.2 U79.8(NFAULT)
N33325781: RJ28.2 U77.27(MODE0)
N33325790: RJ30.2 U77.26(RFB)
N33325799: RJ29.2 U77.54(VODSEL)
N33329532: J25.11 TP67.1(TP)
N33330487: R445.2 U27.G3(GPMC_CS3/QSPI1_CS1/VIN1A_CLK0/V)
N33333072: R249.2 U26.7(VREF2) U26.8(EN)
N33357651: R447.1 U27.AC10(WAKEUP0/DCAN1_RX/GPIO1_0/SYS_NI)
N33390062: C569.2 R448.2 R449.2 R450.2
N33412406: R600.1 U602.3(CLKIN)
N33413294: C608.1 U601.6(CT)
N33413462: Q600.3(D2) R605.1
N33413491: Q600.5(G2) Q600.6(D2) R606.1
N33414534: L34.2 U42.7(SW)
N33414592: R143.1 U42.5(PG)
N33414630: C220.2 R140.1 R141.2 U42.3(FB)
N33426865: R218.1 SW2.3(B2)
N33434554: U78.3(AINL) U78.4(AINR)
N33509599: D25.ANODE1 D25.ANODE2 L604.2 Q603.5(D) R624.2
N33509800: R620.2 U606.30(GD)
N33509804: Q603.4(G) R620.1
N33509815: C630.1 U606.1(C1P)
N33509819: C630.2 U606.2(C1N)
N33509835: Q603.1(S) R621.2 R622.2
N33509839: C631.2 R621.1 U606.28(ISENSE)
N33509953: C634.2 U606.31(CPUMP)
N33510014: C637.2 C638.2 R625.2 U606.24(OUT2) U606.25(OUT1)
N33510050: C639.2 C640.2 R626.2 U606.21(OUT4) U606.22(OUT3)
N33510080: R623.2 U606.7(ISET)
N33529839: C636.2 R624.1
N33635218: R627.1 U77.34(OB_C-)
N33635221: R627.2 U77.33(OB_C+)
N3026308320: R101.2 U27.B11(VIN2A_D12/RGMII1_TXC/VOUT2_D11/)

Pads without a net: J7 4; J14 10 11 14 18 20 22 24 26 28 30 32 34 36 38 40 42 44 46 48 50 52 54 55 56 59 60; J17 9 13 14; NOREF 1; NOREF#6 1; NOREF#10 1; NOREF#11 1; NOREF#12 1; NOREF#13 1; NOREF#15 1; NOREF#16 1; P1 14; P9 1 3 6 8 10 17 18 19 20 21 22 23 25 26 27 28 29 31 33 35 37 39; P10 11 12 13 14; Q602 1 2 6; U16 3 5; U17 14 15 16 17 19 20 21 22; U23 J1 J9 L1 L9; U27 A19 A20 A21 A22 A23 AA2 AA3 AA4 AA5 AA6 AA11 AB6 AB7 AB9 AC3 AC4 AC5 AC6 AC8 AD3 AD4 AD6 AD7 AD9 AE3 AE5 AE6 AE8 B14 B15 B18 B19 B20 B21 B22 B23 B24 C14 C16 C17 C19 C20 C24 C25 D14 D16 D17 D19 D20 D24 D25 E16 E17 E19 E24 E25 F2 F3 F6 F16 F25 G1 G2 G4 G5 G6 G20 G24 G25 H2 H3 H4 H5 H6 H21 H24 J24 J25 K5 K6 K20 K22 K23 L4 L5 L6 L19 L20 L25 M24 M25 N1 N2 N3 N4 N5 N6 N23 N25 P1 P2 P3 P4 P5 R1 R2 T1 T2 T3 T4 T5 U1 U2 U4 U6 V5; U29 J1 J9 L1 L9; U31 A1 A2 A9 A10 B1 B10 D2 D3 D4 D5 D6 D7 D8 D9 E2 E3 E5 E6 E7 E8 E9 H4 H5 H6 H7 J2 J3 J4 J6 J7 J8 J9 K4 K5 K6 K7 L5 L6 M2 M3 M6 M8 M9 N4 N5 N6 N7 P4 P7 T1 T10 U1 U2 U9 U10; U40 6 9 14 17 18 19 20 21 34 35; U52 3 5 6 7 8 9 10 12 13 21 22 23 25 27 28 29 31 32; U66 2; U67 2; U68 2; U69 2 3; U76 1; U77 14 15 17 29 51 63; U78 5 17; U79 11; U600 2 3; U603 4; U605 4; U606 4 8 9 14 32

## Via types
v1: diameter 0.508, hole 0.254, TOP to BOTTOM, 1468 vias
v2: diameter 0.457, hole 0.203, TOP to BOTTOM, 285 vias
v3: diameter 0.406, hole 0.203, TOP to BOTTOM, 185 vias
v4: diameter 0.61, hole 0.305, TOP to BOTTOM, 6 vias

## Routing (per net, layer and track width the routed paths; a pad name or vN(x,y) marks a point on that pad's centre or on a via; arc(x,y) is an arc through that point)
1V8_I2C1_SCL: length 16.4
  TOP w0.127: v1(53.98,122.17) 53.73,122.42 U26.3
  LY4 w0.133: v1(53.98,122.17) 54.74,121.41 54.74,116.46 57.66,113.54 v1(57.66,111.12)
  BOTTOM w0.127: P9.2 57.78,111.24 v1(57.66,111.12) ; v1(53.98,122.17) R245.2
1V8_I2C1_SDA: length 17.6
  TOP w0.127: U26.4 53.71,122.92 v1(53.98,123.19)
  LY4 w0.133: v1(58.42,111.16) 58.42,113.54 55.24,116.71 55.24,121.92 v1(53.98,123.19)
  BOTTOM w0.127: v1(53.98,123.19) R246.2 ; v1(58.42,111.16) 58.28,111.31 P9.4
1V8_RSTOUTN: length 78.3
  TOP w0.127: v1(73.41,71.88) 73.15,71.63 73.15,65.28 73.79,64.64 73.79,62.48 75.18,61.09 75.44,61.09 75.82,60.71 75.82,60.07 74.93,59.18 v1(74.04,59.18)
  TOP w0.305: U31.M5 v1(79.77,59.74)
  LY3 w0.133: v1(74.04,59.18) 74.42,59.56 78.23,59.56 78.47,59.32 79.35,59.32 v1(79.77,59.74)
  BOTTOM w0.127: R296.1 80.01,59.98 v1(79.77,59.74) ; v1(73.41,71.88) 73.41,89.41 77.85,93.85 77.85,96.77 75.56,99.06 75.56,106.3 73.66,108.2 64.77,108.2 62.27,110.7 P9.14
  BOTTOM w0.14: U54.4 73.69,58.83 v1(74.04,59.18)
GND: length 880.8
  TOP w0.203: U17.5 45.01,113.74 v1(44.96,113.79) ; U27.M16 U27.L15 U27.M14 U27.L13 U27.M12 ; U17.13 v1(49.38,111.73) ; U27.Y16 U27.AA15 ; U27.P11 U27.N12 ; U27.K13 U27.J14 ; U17.18 49.08,113.74 v1(49.4,113.41) ; U27.P15 U27.N16 U27.N17 ; U27.K11 U27.J10 ; U35.8 v1(11.81,44.58) ; U27.N20 U27.P19
  TOP w0.254: U27.Y16 v3(47.25,86.27) U27.Y17 ; U27.N20 v3(44.65,81.72) U27.M20 ; U27.M12 v3(50.5,81.72) U27.N12 ; U602.4 v1(39.38,49.66) ; U27.AC11 v3(50.5,88.22) 50.51,88.22 U27.AB11 ; U27.A25 41.73,73.84 41.75,73.82 v2(41.75,73.69) ; U27.T18 v3(46.6,83.67) U27.R18 v3(45.95,83.67) U27.R19 v3(45.95,83.02) U27.P19 ; U27.T18 U27.U17 v3(47.25,84.97) ; U27.T18 U27.U19 v3(45.3,84.97) U27.V19 45.87,85.54 v3(45.95,85.62) 45.87,85.7 U27.W19 ; U27.U12 v3(50.5,84.32) U27.T12 ; U27.U12 U27.V11 U27.U10 51.59,84.54 51.59,84.1 U27.T10 ; U27.U12 U27.V13 U27.U14 ; U27.M8 v3(52.45,81.07) ; v3(52.45,81.07) U27.L8 U27.K9 U27.J10 v3(51.8,79.12) U27.H10 ; v3(52.45,81.07) U27.M9 ; U27.U16 U27.V15 U27.U14 ; U27.U16 v3(47.25,84.97) ; U27.U16 v3(47.9,84.32) U27.T16 ; v1(5.02,79.01) C98.2 v1(7.43,79.01) ; U22.2 v1(17.65,110.24) ; v3(47.25,84.97) U27.V17 ; R76.2 v1(11.68,72.9) ; U35.4 11.31,49.01 v1(10.92,49.4) ; C91.2 14.29,85.1 v1(14.27,85.12) ; v1(16.35,118.9) 16.57,119.13 C81.2 ; U27.U14 v3(49.2,84.32) U27.T14 ; U27.H8 v3(53.1,78.47) U27.G8 ; U22.4 v1(17.65,112.78) ; U27.G16 v3(47.9,78.47) U27.H16 ; U27.V8 v3(52.45,85.62) U27.V9 v3(51.8,85.62) U27.W9 ; 36.83,52.32 U602.24 ; U22.1 v1(17.65,108.97) ; U27.J12 v3(50.5,79.12) U27.H12 ; U27.AE15 48.26,89.87 v3(48.26,90.3) ; U602.11 42.42,52.32 ; v1(7.24,86.26) C89.2 v1(4.83,86.26) ; U27.H19 v3(45.95,78.47) U27.H18 ; R64.2 v1(11.68,87.19) ; U22.3 v1(17.65,111.51) ; U27.A1 v2(57.73,73.85) ; v3(49.85,88.87) 49.53,88.54 U27.AC13 ; U29.G8 v2(16.71,75.31) ; U27.G13 U27.H14
  TOP w0.305: C410.2 88.27,82.42 v1(89.79,83.95) ; J14.61 v1(77.72,48.64) J14.62 v1(71.5,48.64) J14.63 v1(65.28,48.64) J14.64 ; 33.65,26.54 U18.3 33.65,21.84 v1(33.4,21.59) 32.64,21.59 32.39,21.84 U18.9 30.1,21.84 v1(29.21,22.73) 29.08,22.86 29.08,23.88 28.75,24.21 C45.2 ; 33.65,26.54 C53.2 R39.1 ; 33.65,26.54 C54.1 32.89,27.18 v1(33.02,27.3) 32.51,27.81 30.65,27.81 29.87,27.03 29.87,26.57 R36.1 ; U27.K11 v3(51.15,80.42) U27.L11 ; U29.J2 v2(14.31,80.9) ; U29.D8 v2(19.11,75.31) ; U23.P9 v2(10.31,88.73) ; U27.P11 v3(51.15,83.02) U27.R11 ; C561.2 v1(21.84,57.15) ; v1(89.79,86.23) 89.03,87 C568.2 C429.2 ; U604.4 73.38,95.28 v1(73.41,95.25) ; U29.M9 v2(11.91,74.51) ; U31.H9 v1(84.78,64.75) ; U23.J2 v2(14.31,95.13) ; U23.D8 v2(19.11,89.53) ; C545.2 111.76,93.98 v1(111.25,94.49) ; v1(29.21,16.51) 29.72,16.51 30.15,16.94 C29.2 30.15,17.09 29.72,17.53 v1(29.21,17.53) ; R409.2 v1(119.25,88.14) ; U23.E8 v2(18.31,89.53) ; U27.Y7 v3(53.75,86.92) U27.AA7 ; U27.AB8 v3(53.1,87.57) ; v2(57.53,90.42) 57.53,90.04 U27.AE1 ; U23.T1 v2(8.71,95.93) ; U27.K13 v3(49.2,80.42) U27.L13 ; U23.P1 v2(10.31,95.93) ; U23.A9 v2(21.51,88.73) ; U23.G1 v2(16.71,95.93) ; C43.1 C48.1 ; C48.1 38.99,24 v1(39.12,23.88) ; C48.1 C51.1 ; U31.P9 v1(84.78,57.74) ; U29.T1 v2(8.71,81.7) ; U29.G9 v2(16.71,74.51) ; v1(86.23,93.73) C122.2 R444.2 ; U31.G9 v1(84.78,65.75) ; C562.2 v1(21.84,45.47) ; U29.P9 v2(10.31,74.51) ; U29.E2 v2(18.31,80.9) ; v1(111.25,91.95) 111.76,91.44 C544.2 ; v1(94.36,86.23) 94.49,86.36 R443.2 ; v1(111.25,97.03) 111.76,96.52 C542.2 ; U601.5 v1(72.72,32.69) ; v1(112.65,80.52) 112.65,81.03 C546.2 113.41,81.03 v1(113.41,80.52) ; C82.2 12.89,98.62 v1(12.32,99.19) ; v1(101.61,47.5) 101.04,47.5 C212.2 101.04,46.74 v1(101.61,46.74) ; Q600.1 76.98,94.85 v1(77.22,94.61) ; U31.G7 v1(82.77,65.75) ; C129.2 v1(101.47,78.61) ; P1.2 v1(33.22,121.06) ; U23.B3 v2(20.71,94.33) ; Y2.2 v1(93.27,45.9) ; U70.5 v1(108.64,85.93) ; U23.E2 v2(18.31,95.13) ; U27.Y14 v3(48.55,86.92) U27.AA15 ; U29.B3 v2(20.71,80.1) ; U23.M1 v2(11.91,95.93) ; U27.K15 v3(47.9,80.42) U27.L15 ; P1.8 v1(36.22,121.06) ; U78.6 v1(20.35,50.44) 20.32,50.42 C567.2 ; U23.D1 v2(19.11,95.93) ; U31.G4 v1(78.77,65.75) ; U29.P1 v2(10.31,81.7) ; U23.F9 v2(17.51,88.73) ; C547.2 v1(107.82,86.49) ; U29.E1 v2(18.31,81.7) ; P1.17 v1(40.72,121.06) ; C608.2 v1(73.53,32.89) ; U27.M14 49.2,81.72 U27.N14 48.88,82.04 v3(49.2,82.37) 49.53,82.69 U27.P13 v3(49.85,83.02) U27.R13 ; U31.G6 v1(81.77,65.75) ; U29.E8 v2(18.31,75.31) ; v1(74.17,97.79) 73.66,97.79 C611.1 73.66,97.03 v1(74.17,97.03) ; U31.L3 v1(77.77,60.74) ; U602.14 41.66,54.87 v1(41.78,54.99) ; R32.2 v1(42.55,110.62) ; U27.T8 v3(52.45,83.67) U27.R8 ; U31.M4 v1(78.77,59.74) ; U27.P17 v3(46.6,82.37) U27.N17 ; v1(23.5,79.86) C96.2 v1(24.79,79.86) ; v1(95,48.27) 95,48.26 95.17,48.08 Y2.4 ; U23.G9 v2(16.71,88.73) ; U31.J5 v1(79.77,63.75) ; C541.2 115.19,94.74 C540.2 114.68,94.49 v1(114.17,95) ; U23.B1 v2(20.71,95.93) ; U29.F9 v2(17.51,74.5) ; U31.H2 v1(76.77,64.75) ; U23.E1 v2(18.31,95.93) ; U78.1 20.6,52.93 v1(20.32,53.21) ; U29.M1 v2(11.91,81.7) ; v1(97.41,81.92) 97.03,82.3 C409.2 ; U23.J8 v2(14.31,89.53) ; v1(23.62,54.48) 23.36,54.22 U78.21 ; DS1.1 v1(122.02,40.54) ; U29.J8 v2(14.31,75.31) ; C543.2 111.76,88.9 v1(111.25,89.41) ; U27.M18 v3(45.95,81.07) U27.L18 ; U29.A9 v2(21.51,74.5) ; U27.P9 v3(52.45,83.02) U27.R9 ; v1(85.2,46.86) 85.78,46.86 C189.2 85.78,47.62 v1(85.2,47.62) ; J14.16 v1(75.25,44.13) ; U31.G2 v1(76.77,65.75) ; U78.11 23.86,49.16 24,49.02 v1(24,48.51) ; P1.5 v1(34.72,121.06) ; U27.J17 v3(46.6,79.77) U27.K17 ; C604.2 v4(71.75,34.47) ; U27.AA8 v3(52.45,86.92) U27.AA9 ; U27.H14 v3(48.55,79.12) U27.J14 ; U27.M16 v3(47.9,81.72) U27.N16 ; U27.P15 v3(48.55,83.02) U27.R15 ; U31.L8 v1(83.77,60.74) ; C617.1 v1(69.85,91.95) ; U31.G5 v1(79.77,65.75) ; U29.T9 v2(8.71,74.5) ; U31.G3 v1(77.77,65.75) ; U29.B1 v2(20.71,81.7) ; U23.T9 v2(8.71,88.73) ; U23.B9 v2(20.71,88.73) ; Q600.4 v1(74.97,93.64) ; U29.B9 v2(20.71,74.51) ; U78.24 v1(21.08,53.59) ; v1(5.46,92.79) C84.2 v1(6.96,92.76) ; Q602.4 v1(109.56,101.43) ; U26.1 v1(53.71,121.43) ; U79.2 v1(101.6,56.77) ; v1(14.86,48.01) v1(15.88,48.01) ; U23.G8 v2(16.71,89.53) ; U31.M7 v1(81.78,60.73) ; v3(49.2,87.57) U27.AA13 ; U23.M9 v2(11.91,88.73) ; P1.11 v1(37.72,121.06) ; U29.D1 v2(19.11,81.7) ; U31.P2 v1(76.77,57.74) ; U27.AE25 41.73,89.97 v2(41.4,90.3) ; U31.G8 v1(83.77,65.75) ; R104.1 v1(45.72,62.61) ; U29.G1 v2(16.71,81.7) ; J14.58 v1(64.75,44.09) ; v1(64.75,53.09) J14.57
  TOP w0.356: v1(43.56,52.32) v2(42.67,52.32) 42.42,52.32 ; v1(35.69,52.32) v2(36.44,52.32) 36.83,52.32
  TOP w0.381: v2(36.13,73.28) 37.01,73.28 C108.2 v2(38.34,73.48)
  TOP w0.508: C2.2 48.92,36.2 ; C2.2 47.62,34.9 ; C2.2 47.62,37.49 ; C2.2 46.33,36.2 ; C118.2 v1(65.91,68.62) ; 43.89,125.41 P1.MTG3 ; P1.MTG3 45.31,123.98 ; P1.MTG3 45.31,126.83 ; P1.MTG3 46.74,125.41 ; v1(117.73,110.11) v1(116.71,110.11) v1(115.7,110.11) 115.3,109.71 U606.29 111.66,109.71 C634.1 ; C560.2 v1(20.32,44.37) ; C563.2 v1(25.4,44.37) ; v1(6.78,56.26) 7.29,56.26 C144.1 7.29,55.24 v1(6.78,55.24) ; v1(38.2,112.85) U10.2 ; v1(6.99,47.5) C161.1 C158.1 ; 14.1,51.44 14.23,51.3 v1(14.91,51.3) ; J17.11 119.69,61.9 ; TP60.1 v1(130.3,113.67) ; v1(38.73,114.81) U5.2 ; U606.10 119.79,108.11 v1(119.76,108.08) ; P1.MTG1 44.7,121.93 ; P1.MTG1 46.13,120.51 ; P1.MTG1 44.7,119.08 ; P1.MTG1 43.28,120.51 ; C83.2 v1(23.24,116.71) ; C119.2 v1(67.44,67.69) ; v1(16.08,54.48) 15.7,54.48 C153.1 15.7,53.47 v1(16.08,53.47) ; C73.2 v1(16.38,124.21) ; C114.2 v1(62.99,71.12) ; 28.19,125.41 P1.MTG4 ; P1.MTG4 29.62,126.83 ; P1.MTG4 29.62,123.98 ; P1.MTG4 31.04,125.41 ; U606.12 120.16,109.71 v1(119.76,110.11) 120.16,110.51 U606.13 ; 38.86,47.37 v1(39.62,47.37) ; C71.2 v1(11.81,124.21) ; U606.20 v1(118.13,115.42) ; J7.5 v1(9.65,117.53) ; J17.12 119.69,63.91 ; 28.8,120.51 P1.MTG2 ; P1.MTG2 30.23,121.93 ; P1.MTG2 31.65,120.51 ; P1.MTG2 30.23,119.08 ; C633.1 v1(118.62,103.5) R623.1 ; R118.1 C160.1 v1(16.64,48.51) ; C1.2 88.93,36.2 ; C1.2 87.63,34.9 ; C1.2 87.63,37.49 ; C1.2 86.33,36.2 ; U7.2 v1(32.61,112.88) ; TP16.1 v1(26.54,124.97) ; J1.2 106.05,79.91 ; J1.2 106.05,77.57 ; J1.2 107.21,78.74 ; J1.2 104.88,78.74 ; U9.2 v1(36.7,112.84) ; C559.2 v1(18.29,44.37) ; v1(41.21,114.81) U6.2 ; C78.2 v1(20.9,121.97) ; D27.2 v1(115.06,74.17) ; v1(16.08,56.52) 15.7,56.52 C143.1 15.7,55.5 v1(16.08,55.5) ; C120.2 v1(69.47,67.69) ; v1(6.78,54.1) 7.29,54.1 C154.1 7.29,53.09 v1(6.78,53.09) ; 8.26,45.47 v1(7.49,45.47) ; C558.2 v1(20.32,58.37) ; C565.2 v1(23.37,44.37) ; R52.2 v1(15.24,124.21) ; J17.6 119.69,51.89 ; C72.2 v1(14.1,124.21) ; v1(34.1,112.9) U8.2 ; U606.23 115.73,112.17 v1(115.7,112.14) ; v1(6.78,50.93) 7.29,50.93 C156.1 7.29,51.94 v1(6.78,51.94) ; v1(34.04,52.32) v1(34.92,52.32) v1(35.69,52.32) ; TP39.1 v1(4.06,35.56) ; 14.1,52.45 v1(14.86,52.45) ; U3.2 v1(29.59,114.75) ; D26.2 v1(115.19,83.19) ; v1(32.13,114.81) U4.2 ; C556.2 v1(23.37,58.37) ; R56.1 20.7,117.09 v1(20.95,117.35) ; v1(43.56,52.32) v1(44.32,52.32) ; TP17.1 v1(108.33,44.32) ; C607.2 v1(69.09,32.13) ; J17.5 119.69,49.89
  L2_GND w0.508: P1.MTG2 31.55,120.51 ; P1.MTG2 28.9,120.51 ; P1.MTG2 30.23,119.19 ; P1.MTG2 30.23,121.83 ; 45.31,124.09 P1.MTG3 ; P1.MTG3 45.31,126.73 ; P1.MTG3 43.99,125.41 ; P1.MTG3 46.63,125.41 ; C1.2 88.9,36.2 ; C1.2 86.36,36.2 ; C1.2 87.63,34.92 ; C1.2 87.63,37.47 ; C3.2 48.9,19.05 ; C3.2 46.35,19.05 ; C3.2 47.62,20.32 ; C3.2 47.62,17.78 ; P1.MTG4 30.94,125.41 ; P1.MTG4 29.62,126.73 ; P1.MTG4 29.62,124.09 ; P1.MTG4 28.3,125.41 ; J1.2 106.05,79.81 ; J1.2 107.11,78.74 ; J1.2 104.98,78.74 ; J1.2 106.05,77.67 ; J17.12 119.58,63.91 ; 44.7,119.19 P1.MTG1 ; P1.MTG1 44.7,121.83 ; P1.MTG1 46.03,120.51 ; P1.MTG1 43.38,120.51 ; 87.63,17.78 C23.2 ; C23.2 88.9,19.05 ; C23.2 87.63,20.32 ; C23.2 86.36,19.05 ; J17.11 119.58,61.9 ; C2.2 47.62,37.47 ; C2.2 48.9,36.2 ; C2.2 46.35,36.2 ; C2.2 47.62,34.92 ; J4.2 126.92,34.42 ; J4.2 125.35,35.99 ; J4.2 125.35,32.84 ; J4.2 123.77,34.42 ; J17.6 119.58,51.89 ; J17.5 119.58,49.89
  LY4 w0.508: 46.5,17.92 C3.2 ; C3.2 48.75,17.92 ; C3.2 48.75,20.18 ; C3.2 46.5,20.18 ; C2.2 48.75,35.07 ; C2.2 48.75,37.32 ; C2.2 46.5,35.07 ; C2.2 46.5,37.32 ; 29.06,121.67 P1.MTG2 ; P1.MTG2 31.39,121.67 ; P1.MTG2 29.06,119.35 ; P1.MTG2 31.39,119.35 ; 28.45,126.57 P1.MTG4 ; P1.MTG4 28.45,124.25 ; P1.MTG4 30.78,126.57 ; P1.MTG4 30.78,124.25 ; P1.MTG1 45.87,121.67 ; P1.MTG1 45.87,119.35 ; P1.MTG1 43.54,119.35 ; P1.MTG1 43.54,121.67 ; C1.2 88.76,35.07 ; C1.2 86.5,35.07 ; C1.2 88.76,37.32 ; C1.2 86.5,37.32 ; J4.2 126.69,35.76 ; J4.2 126.69,33.08 ; J4.2 124.01,35.76 ; J4.2 124.01,33.08 ; 119.5,48.9 J17.5 119.5,50.87 ; 105.06,79.72 J1.2 ; J1.2 107.03,77.76 ; J1.2 105.06,77.76 ; 44.15,124.25 P1.MTG3 ; P1.MTG3 46.48,126.57 ; P1.MTG3 46.48,124.25 ; P1.MTG3 44.15,126.57 ; J17.6 119.5,52.87 ; J17.6 117.53,52.87 ; J17.6 119.5,50.91 ; 119.5,62.92 J17.12 119.5,64.89 ; C23.2 88.76,17.92 ; C23.2 88.76,20.18 ; C23.2 86.5,20.18 ; C23.2 86.5,17.92 ; J17.11 119.5,62.88 ; J17.11 119.5,60.92 ; J17.11 117.53,60.92
  LY5_PWR w0.203: v2(58.67,73.33) 59.51,73.33 60.09,72.75 60.09,71.4 60.45,71.04 60.45,69.98 59.94,69.47 59.94,66.55 59.18,65.79 50.93,65.79 50.42,65.28 46.47,65.28 44.07,62.88 44.07,62.73 43.15,61.81 43.15,59.18 42.04,58.06 42.04,56.74 41.78,56.49 v1(41.78,54.99)
  BOTTOM w0.254: U52.24 21.56,121.68 v1(21.8,121.92) ; 12.06,82.42 v2(11.91,81.7) ; U52.20 19.56,121.68 v1(19.93,122.05) ; v2(31.7,85.98) C312.2 v2(31.7,87.33) ; C337.2 v2(18.31,81.7) ; v1(17.91,121.79) 18.06,121.64 U52.17 ; 29.84,75.69 29.08,75.69 29,75.78 v1(28.96,75.78) ; v2(36.19,91.95) C295.2 36.16,91.21 35.79,91.22 v2(35.55,90.98) ; C308.2 v3(48.55,86.92) ; v2(33.48,87.33) C311.2 v2(33.48,85.98) ; v2(38.58,92.05) 39.07,92.54 39.09,92.54 39.39,92.84 v2(39.75,92.84) ; v1(49.38,111.73) 48.97,112.14 C268.2 C269.2 ; v2(36.96,91.44) 37.27,91.44 37.59,91.77 C294.2 37.6,91.77 37.98,92.15 v2(37.98,92.32) ; v2(47.7,68.56) 47.7,68.56 47.71,68.56 ; C383.2 v2(16.71,74.51) ; v3(46.6,82.37) 46.61,82.36 C349.2 ; C382.2 v2(20.71,74.51) ; C336.2 v2(20.71,81.7) ; U52.26 v1(23.35,119.74) ; v2(38.48,84.33) 38.73,84.58 C322.2 ; v3(47.9,81.72) C341.2 ; C305.2 v2(16.71,88.73) ; v2(38.99,90.69) C297.2 v2(38.34,90.04) ; C279.2 v2(18.31,95.93) ; 12.06,96.65 v2(11.91,95.93) ; C278.2 v2(20.71,95.93) ; C388.2 v2(53.39,70.99) ; C304.2 v2(20.71,88.73) ; C298.2 46.03,90.3 v3(48.26,90.3) ; v3(47.25,84.97) C319.2 ; C318.2 v3(52.45,85.62) ; C340.2 v3(50.5,81.72) ; C331.2 38.2,83.68 37.85,84.03 v1(37.85,84.27) ; v2(60.53,71.58) 61.29,71.58 C390.2 ; v3(49.2,84.32) C321.2 ; v3(49.2,80.42) 49.48,80.42 C347.2 ; C332.2 v3(49.85,83.02) ; C300.2 v2(21.51,88.73) ; U52.4 v1(20.06,114.94) ; C309.2 v3(49.2,87.57) ; C378.2 v2(21.51,74.5)
  BOTTOM w0.305: J25.43 v1(87.68,103.38) ; RJ30.3 v1(84.84,86.36) ; 96.19,96.65 v1(96.19,95.89) ; C553.2 R432.2 v1(41.53,28.96) ; v1(16.89,85.65) C314.2 v1(16.84,87.07) ; U76.2 v1(35.69,33.15) ; U68.4 v1(109.99,95.38) ; RJ23.1 v1(84.84,82.55) ; v3(55.7,78.47) 55.22,78.94 C283.2 ; v1(84.78,64.75) 85.09,64.43 C411.2 ; v1(96.16,52.7) 96.93,51.94 96.9,51.94 ; v1(79.77,65.75) 80.11,65.41 C435.2 ; U67.4 v1(109.99,92.84) ; v1(20.8,72.85) C391.2 v1(20.83,71.42) ; RJ20.1 v1(100.46,76.83) ; R437.2 22.1,51.56 v1(22.23,51.69) ; C335.2 45.36,82.42 v3(45.95,83.02) ; C434.2 v1(64.77,67.94) ; v3(53.1,78.47) C357.2 ; P9.16 62.77,111.26 v1(62.91,111.12) ; v1(17.08,73.03) C392.2 17.02,71.45 v1(17.02,71.44) ; 86.19,96.65 v1(86.19,95.89) ; 97.69,96.65 v1(97.69,95.89) ; 87.19,96.65 v1(87.19,95.89) ; RJ29.3 v1(99.44,87.12) ; J25.49 v1(80.44,103.17) ; U54.2 v1(72.52,61.59) 72.9,61.59 73.17,61.33 U54.3 ; C299.2 v1(23.05,88.39) ; U77.25 v1(86.75,85.34) ; C508.2 v1(87.12,45.85) ; RJ28.3 v1(82.04,88.52) ; v1(39.47,78.36) 39.52,78.4 C369.2 ; C503.2 93.52,45.9 v1(93.27,45.9) ; J25.46 v1(95.19,103.38) ; R309.1 75.95,50.29 v1(75.56,49.91) ; RJ18.1 v1(84.84,81.28) ; v1(12.32,83.19) 12.06,84.07 v1(12.32,84.96) ; v3(48.26,90.3) 48.27,90.3 49.02,90.3 ; C552.2 v1(44.83,26.67) ; v1(20.85,85.65) C313.2 v1(20.8,87.07) ; J25.42 v1(85.18,103.38) ; v1(85.25,95.8) 85.19,95.86 85.19,96.65 ; R446.2 v1(107.95,56.77) ; C362.2 v3(51.8,79.12) C370.2 ; v1(21.67,83.24) C326.2 v1(21.64,84.91) ; J25.44 v1(90.18,103.38) ; P9.24 65.77,111.26 v1(65.91,111.12) ; v1(34.8,80.52) 35.31,81.03 C282.2 ; v3(46.6,83.67) 46.35,83.92 46.35,84.07 46.16,84.27 C325.2 ; P9.41 v1(58.74,115.57) v1(65.02,115.57) P9.43 v1(71.25,115.57) P9.44 ; v3(55.5,76.96) 55.5,76.88 C288.2 ; 82.19,96.65 82.19,96.64 82.19,96.04 v1(82.04,95.89) ; C506.2 95.12,48.13 95,48.26 v1(95,48.27) ; U66.4 v1(109.99,90.3) ; R244.1 v1(75.95,88.9) ; J25.47 v1(97.69,103.38) ; C267.2 v1(49.15,116.52) ; C557.2 23.75,52.58 v1(23.88,52.45) ; J25.50 v1(102.44,103.17) ; C509.2 v1(87.12,48.64) ; 88.69,96.65 v1(88.69,95.89) ; R240.1 v1(74.68,88.9) ; R248.1 v1(77.22,88.9) ; v3(52.45,83.67) 52.47,83.68 C342.2 ; v1(21.62,97.36) C272.2 v1(21.62,99.19) ; v1(18.41,97.41) C273.2 v1(18.41,99.19) ; RJ27.3 104.65,60.33 v1(105.41,59.56) C521.2 ; C436.2 v1(76.2,68.83) ; R251.2 v1(78.49,81.28) ; RJ19.1 v1(96.14,77.6) ; R330.2 v1(76.71,44.2) ; v1(12.32,99.19) 12.06,98.3 v1(12.32,97.41) ; C368.2 47.87,78.43 v3(47.9,78.47) ; C367.2 v3(50.5,79.12) ; RJ21.1 v1(97.54,74.8) ; RJ22.1 v1(93.98,74.8) ; R235.2 v1(14.99,110.24) ; C537.2 C536.2 58.88,68.63 v1(59.31,68.2) 59.44,68.2 v1(60.83,66.8) ; C437.2 85.12,65.41 v1(84.78,65.75) ; C427.2 85.09,57.43 v1(84.78,57.74) ; v1(18.67,83.19) C327.2 v1(18.67,84.96) ; C566.2 v1(105.41,65.15) ; v2(44.68,70.61) 44.58,70.72 C374.2 ; R440.1 v1(105.92,61.47) ; v1(68.45,81.15) 68.47,81.17 ; R441.1 v1(99.06,64.9) ; v3(45.3,84.97) 45.3,84.98 C315.2 ; J25.48 v1(100.19,103.38) ; v1(61.41,111.12) 61.27,111.26 P9.12 ; R259.2 v1(81.03,81.28) ; 81.69,96.65 v1(81.03,96.65) ; R401.2 v1(39.12,23.88) ; C275.1 v1(14.99,108.97) ; R608.1 v1(113.16,103) ; D24.2 v1(33.91,32.69) ; J25.45 v1(92.68,103.38) ; J25.41 v1(82.68,103.38) ; C519.2 v1(99.69,45.72) ; 94.69,96.65 v1(94.69,95.89) ; RJ24.1 v1(84.84,85.09) ; RJ25.1 v1(84.84,83.82) ; Q12.1 v1(41.02,30.39) ; v1(94.87,54) 95.38,54.51 C507.2 ; 101.19,96.65 v1(101.85,96.65) ; 90.83,80.64 v1(90.83,79.86) ; 90.19,96.65 v1(90.19,95.89) ; 99.19,96.65 v1(99.19,95.89) ; C428.2 v1(63.37,67.94) ; R222.1 v1(33.02,27.3) ; C518.2 v1(99.69,48.51) ; v1(23.05,74.17) C377.2 ; R603.1 41.91,53.09 v2(42.67,52.32) 41.91,51.56 R604.1 ; RJ16.3 v1(98.68,81.28) ; 100.69,96.65 v1(100.69,95.89) ; C514.2 v1(102.87,56.77) ; R255.2 v1(79.76,81.28) ; Q12.4 v1(39.1,33.13) ; RJ17.3 v1(99.44,84.2) ; 80.39,68.45 v1(80.39,69.22) ; C525.2 v1(112.78,59.82) ; 93.19,96.65 v1(93.19,95.89) ; 91.69,96.65 v1(91.69,95.89) ; U69.4 v1(109.99,87.76)
  BOTTOM w0.381: v2(58.48,96.14) 57.85,96.14 C286.2 ; v2(68.39,77.47) 68.4,77.48 C372.2 ; C344.2 v1(63.02,81.15) ; v2(27.23,86.72) 27.81,86.72 28.09,86.44 C307.2 28.25,85.54 v2(28.2,85.49) ; v1(65.7,88.47) 65.58,88.47 65.58,88.47 C303.2 v1(63.16,88.47) ; v2(36.13,73.28) 36.2,73.34 36.2,73.48 36.74,74.03 C380.2 37.8,74.03 v2(38.34,73.48) ; v2(29.36,81.42) C354.2 v2(29.36,80.12) ; 68.47,81.17 C343.2 ; v3(51.8,85.62) 51.49,86.27 ; 52.7,96.65 53.85,96.65 ; C406.2 v1(36.07,68.45) ; C306.2 54.48,86.87 54.48,86.87 53.8,86.87 v3(53.75,86.92) ; C348.2 47.9,80.77 v3(47.9,80.42) ; v2(25.73,80.11) C352.2 v2(25.73,81.45) ; C302.2 v1(59.94,88.46) ; v2(40.94,73.48) C385.2 39.21,71.79 v2(39.1,71.69) ; C430.2 v1(70.74,63.5) ; v2(27.51,80.14) C351.2 v2(27.51,81.45) ; C364.2 v3(46.6,79.77) ; C431.2 v1(69.6,63.5)
  BOTTOM w0.406: 61.72,80.39 62.1,80.77 v1(62.1,81.03) ; v1(68.45,81.15) E4.2 65.73,81.15 v1(65.7,81.12) 65.68,81.15 C344.2 ; C407.2 40.26,67.86 v2(40.28,67.88) E7.2 40.28,70.54 v1(40.44,70.7) ; v2(44.68,70.61) E6.2 44.68,67.83 v2(44.69,67.83) 44.7,67.81 C408.2 ; v2(51.24,68.55) C402.2 v2(51.24,71) ; v2(58.48,96.14) E1.2 v2(61.16,96.14) ; v2(53.39,70.99) 53.38,70.98 C403.2 53.38,68.47 v2(53.37,68.46) ; v1(59.94,88.46) 59.96,88.44 C551.2 v1(62.36,88.44) 63.13,88.44 v1(63.16,88.47) ; C301.2 v1(68.5,88.47) 68.49,88.46 E2.2 65.72,88.46 v1(65.7,88.47) ; C395.2 47.37,71.3 v2(47.67,71) 47.7,70.97 C401.2 v2(47.7,68.56) ; C320.2 60.07,86.61 v1(60.45,86.61) ; C334.2 v1(60.33,81.88) ; v2(65.66,77.47) E5.2 v2(68.39,77.47) ; v2(65.66,79.1) 65.62,79.14 C373.2 63.25,79.14 63.21,79.1 v2(63.19,79.1) ; 53.85,96.65 53.85,97.03 54.31,97.49 C281.2 v1(55.5,98.42) ; C345.2 C333.2 v1(61.34,81.88) ; v1(45.8,70.77) 45.8,70.77 C394.2 ; v3(44.65,81.72) 45.16,81.72 C356.2 ; C412.2 v1(45.72,65.28) ; C329.2 60.2,84.56 v1(60.2,84.58) C432.2 ; C379.2 v2(58.67,73.33) 59.55,72.46 59.55,72.43 60.41,71.58 v2(60.53,71.58) ; C324.2 68.44,84.82 v1(68.43,84.84) E3.2 v1(65.63,84.84) 63.96,84.84 C323.2 v1(62.61,84.82) ; v2(39.25,95.01) C289.2 v2(41.79,95.01) ; C426.2 v1(51.29,64.64) ; C358.2 60.71,80.14 v1(60.96,80.39)
  BOTTOM w0.508: C287.2 C277.2 v1(39.75,76.07) ; TP66.1 v1(109.6,68.2) ; TP64.1 v1(2.92,14.86) ; C442.1 v1(70.48,61.09) ; TP65.1 v1(129.92,13.08) ; TP63.1 v1(24.89,124.97)
  BOTTOM w0.635: P1.MTG3 46.74,125.41 ; P1.MTG3 43.89,125.41 ; P1.MTG3 45.31,126.83 ; P1.MTG3 45.31,123.98 ; 104.88,78.74 J1.2 ; J1.2 107.21,78.74 ; J1.2 106.05,77.57 ; J1.2 106.05,79.91 ; 30.23,119.08 P1.MTG2 ; P1.MTG2 30.23,121.93 ; P1.MTG2 31.65,120.51 ; P1.MTG2 28.8,120.51 ; C2.2 47.62,38.46 ; C2.2 49.89,36.2 ; C2.2 45.36,36.2 ; C2.2 47.62,33.93 ; C23.2 87.63,21.31 ; C23.2 87.63,16.79 ; C23.2 85.37,19.05 ; C23.2 89.89,19.05 ; P1.MTG1 44.7,121.93 ; P1.MTG1 46.13,120.51 ; P1.MTG1 44.7,119.08 ; P1.MTG1 43.28,120.51 ; C3.2 47.62,21.31 ; C3.2 49.89,19.05 ; C3.2 47.62,16.79 ; C3.2 45.36,19.05 ; J17.11 119.69,61.9 ; J17.5 119.69,49.89 ; C1.2 89.89,36.2 ; C1.2 87.63,33.93 ; C1.2 87.63,38.46 ; C1.2 85.37,36.2 ; 29.62,123.98 P1.MTG4 ; P1.MTG4 29.62,126.83 ; P1.MTG4 31.04,125.41 ; P1.MTG4 28.19,125.41 ; 125.35,32.74 J4.2 ; J4.2 123.67,34.42 ; J4.2 127.03,34.42 ; J4.2 125.35,36.09 ; J17.12 119.69,63.91 ; J17.6 119.69,51.89
  vias: v1(1.27,126.36) v1(1.27,121.28) v1(1.27,118.75) v1(1.27,116.2) v1(1.27,113.03) v1(1.27,110.49) v1(1.27,107.95) v1(1.27,105.41) v1(1.27,102.87) v1(1.27,100.33) v1(1.27,97.79) v1(1.27,95.25) v1(1.27,92.71) v1(1.27,90.17) v1(1.27,87.63) v1(1.27,85.09) v1(1.27,82.55) v1(1.27,80.01) v1(1.27,77.47) v1(1.27,74.93) v1(1.27,72.39) v1(1.27,69.85) v1(1.27,67.31) v1(1.27,64.77) v1(1.27,62.23) v1(1.27,59.69) v1(1.27,57.15) v1(1.27,54.61) v1(1.27,52.07) v1(1.27,49.53) v1(1.27,46.99) v1(1.27,44.45) v1(1.27,41.91) v1(1.27,39.37) v1(1.27,36.83) v1(1.27,34.29) v1(1.27,31.75) v1(1.27,29.21) v1(1.27,26.67) v1(1.27,24.13) v1(1.27,21.59) v1(1.27,19.05) v1(1.27,16.51) v1(1.27,13.97) v1(1.27,11.43) v1(3.81,11.43) v1(4.45,126.36) v1(6.35,11.43) v1(6.99,126.36) v1(8.89,11.43) v1(9.53,126.36) v1(11.05,47.5) v1(11.05,46.48) v1(11.43,11.43) v1(11.81,46.99) v1(12.06,126.36) v1(12.57,47.5) v1(12.57,46.48) v1(13.97,11.43) v1(14.61,126.36) v1(14.99,20.32) v1(16,20.32) v1(16.51,11.43) v1(16.89,22.99) v1(16.89,22.1) v1(17.02,28.32) v1(17.02,25.27) v1(17.02,24.38) v1(17.14,126.36) v1(18.03,30.61) v1(18.03,29.72) v1(18.03,28.83) v1(18.03,24.89) v1(18.03,23.88) v1(18.03,22.99) v1(18.03,22.1) v1(18.67,119.63) v1(18.67,118.49) v1(18.67,117.35) v1(19.05,11.43) v1(19.68,126.36) v1(19.81,119.63) v1(19.81,118.49) v1(19.81,117.35) v1(20.19,21.08) v1(20.19,20.19) v1(20.95,119.63) v1(20.95,118.49) v1(21.59,11.43) v1(22.23,126.36) v1(23.11,51.69) v1(23.88,50.93) v1(24.13,11.43) v1(24.77,126.36) v1(26.67,11.43) v1(27.3,126.36) v1(28.57,31.37) v1(28.68,29.82) v1(28.7,29.08) v1(28.83,110.36) v1(28.96,112.78) v1(29.21,11.43) v1(29.34,30.61) v1(29.46,29.08) v1(29.59,29.84) v1(30.73,116.33) v1(30.73,57.28) v1(30.73,47.37) v1(31.75,108.2) v1(31.75,57.28) v1(31.75,47.37) v1(31.75,11.43) v1(31.88,110.62) v1(32.13,117.86) v1(32.51,56.26) v1(32.51,48.39) v1(32.64,22.35) v1(32.64,20.83) v1(33.02,126.36) v1(33.4,57.66) v1(33.4,47.12) v1(33.91,117.86) v1(34.16,22.35) v1(34.16,20.83) v1(34.29,11.43) v1(34.42,54.61) v1(34.42,53.34) v1(34.42,51.44) v1(34.42,50.16) v1(35.43,117.86) v1(35.43,110.24) v1(35.43,31.37) v1(35.56,126.36) v1(35.56,108.2) v1(36.83,11.43) v1(36.96,117.86) v1(38.1,126.36) v1(38.99,117.22) v1(38.99,110.49) v1(39.12,108.2) v1(39.37,11.43) v1(40.26,116.08) v1(40.64,126.36) v1(41.53,57.78) v1(41.53,57.02) v1(41.78,108.2) v1(41.91,112.9) v1(41.91,11.43) v1(43.18,126.36) v1(44.45,11.43) v1(44.83,54.61) v1(44.83,53.34) v1(44.83,51.44) v1(44.83,50.16) v1(44.96,57.66) v1(45.21,52.32) v1(45.85,57.66) v1(45.85,47.12) v1(46.74,56.26) v1(46.74,48.39) v1(46.99,11.43) v1(47.5,57.28) v1(47.5,47.37) v1(48.26,126.36) v1(48.51,57.28) v1(48.51,47.37) v1(49.53,11.43) v1(50.8,126.36) v1(52.07,11.43) v1(53.34,126.36) v1(54.61,11.43) v1(55.88,126.36) v1(57.15,11.43) v1(58.42,126.36) v1(59.69,11.43) v1(60.96,126.36) v1(62.23,11.43) v1(63.5,126.36) v1(64.77,11.43) v1(65.66,102.74) v1(65.79,96.14) v1(65.79,95.38) v1(66.04,126.36) v1(67.31,11.43) v1(68.58,126.36) v1(68.83,24.51) v1(69.22,23.5) v1(69.22,22.73) v1(69.22,21.34) v1(69.22,20.57) v1(69.6,24.51) v1(69.85,11.43) v1(70.36,26.29) v1(71.12,126.36) v1(72.39,11.43) v1(72.52,102.74) v1(73.66,126.36) v1(73.79,26.54) v1(74.93,11.43) v1(76.2,126.36) v1(77.47,11.43) v1(78.74,126.36) v1(80.01,11.43) v1(81.28,126.36) v1(82.55,11.43) v1(83.82,126.36) v1(85.09,11.43) v1(86.23,124.08) v1(86.23,122.94) v1(86.23,121.79) v1(86.36,126.36) v1(87.63,11.43) v1(88.9,126.36) v1(89.79,85.09) v1(90.17,11.43) v1(90.42,124.46) v1(90.93,87.38) v1(90.93,86.23) v1(90.93,85.09) v1(90.93,83.95) v1(90.93,82.8) v1(91.44,126.36) v1(91.44,124.46) v1(92.08,87.38) v1(92.08,86.23) v1(92.08,85.09) v1(92.08,83.95) v1(92.08,82.8) v1(92.58,124.46) v1(92.71,11.43) v1(93.22,87.38) v1(93.22,86.23) v1(93.22,85.09) v1(93.22,83.95) v1(93.22,82.8) v1(93.57,52.7) v1(93.98,126.36) v1(94.36,85.09) v1(94.36,83.95) v1(94.74,124.46) v1(94.87,52.7) v1(94.87,51.41) v1(95.25,11.43) v1(95.89,124.46) v1(96.52,126.36) v1(97.03,124.46) v1(97.79,11.43) v1(99.06,126.36) v1(100.33,11.43) v1(100.71,125.35) v1(101.6,126.36) v1(101.73,34.16) v1(101.73,32.89) v1(101.73,31.62) v1(101.85,125.35) v1(102.87,11.43) v1(103,125.35) v1(103.5,35.18) v1(103.5,30.48) v1(104.14,126.36) v1(105.41,11.43) v1(106.17,115.44) v1(106.17,114.3) v1(106.68,126.36) v1(107.44,115.44) v1(107.44,114.3) v1(107.95,125.35) v1(107.95,11.43) v1(109.09,125.35) v1(109.22,126.36) v1(109.73,46.86) v1(110.24,125.35) v1(110.36,17.4) v1(110.49,11.43) v1(111.63,17.4) v1(111.76,126.36) v1(112.01,45.21) v1(113.03,11.43) v1(114.09,91.74) v1(114.3,126.36) v1(115.44,91.31) v1(115.57,11.43) v1(115.7,111.12) v1(115.7,109.09) v1(115.7,108.08) v1(116.71,112.14) v1(116.71,111.12) v1(116.71,109.09) v1(116.71,108.08) v1(116.84,126.36) v1(117.73,112.14) v1(117.73,111.12) v1(117.73,109.09) v1(117.73,108.08) v1(118.11,11.43) v1(118.75,112.14) v1(118.75,111.12) v1(118.75,110.11) v1(118.75,109.09) v1(118.75,108.08) v1(119.38,126.36) v1(119.76,112.14) v1(119.76,111.12) v1(119.76,109.09) v1(120.65,11.43) v1(121.92,126.36) v1(123.19,11.43) v1(124.08,122.05) v1(124.46,126.36) v1(125.22,122.05) v1(125.73,11.43) v1(126.36,122.05) v1(127,126.36) v1(128.27,11.43) v1(129.54,126.36) v1(132.08,126.36) v1(132.08,123.83) v1(132.08,121.28) v1(132.08,118.75) v1(132.08,116.2) v1(132.08,113.67) v1(132.08,111.12) v1(132.08,108.58) v1(132.08,106.05) v1(132.08,103.5) v1(132.08,99.19) v1(132.08,97.16) v1(132.08,94.61) v1(132.08,92.71) v1(132.08,90.17) v1(132.08,88.52) v1(132.08,85.09) v1(132.08,82.55) v1(132.08,80.01) v1(132.08,77.47) v1(132.08,74.93) v1(132.08,72.39) v1(132.08,69.85) v1(132.08,67.31) v1(132.08,64.77) v1(132.08,62.23) v1(132.08,59.69) v1(132.08,57.15) v1(132.08,54.61) v1(132.08,52.07) v1(132.08,49.53) v1(132.08,46.99) v1(132.08,44.45) v1(132.08,41.91) v1(132.08,39.37) v1(132.08,36.83) v1(132.08,34.29) v1(132.08,31.75) v1(132.08,29.21) v1(132.08,26.67) v1(132.08,24.13) v1(132.08,21.59) v1(132.08,19.05) v1(132.08,16.51) v1(132.08,13.97) v1(132.08,11.43) v2(39.62,53.16) v2(39.62,52.32) v2(39.62,51.49) v4(71.32,26.29) v4(71.75,33.6) v4(72.19,26.29) v4(109.6,85.01) v4(109.6,84.15)
